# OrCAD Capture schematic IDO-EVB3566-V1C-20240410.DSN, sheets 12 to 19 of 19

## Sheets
12 P18. UART/RS232: size A3; title: IDO-SBC3566-V1B; note: UART/RS232/RS485
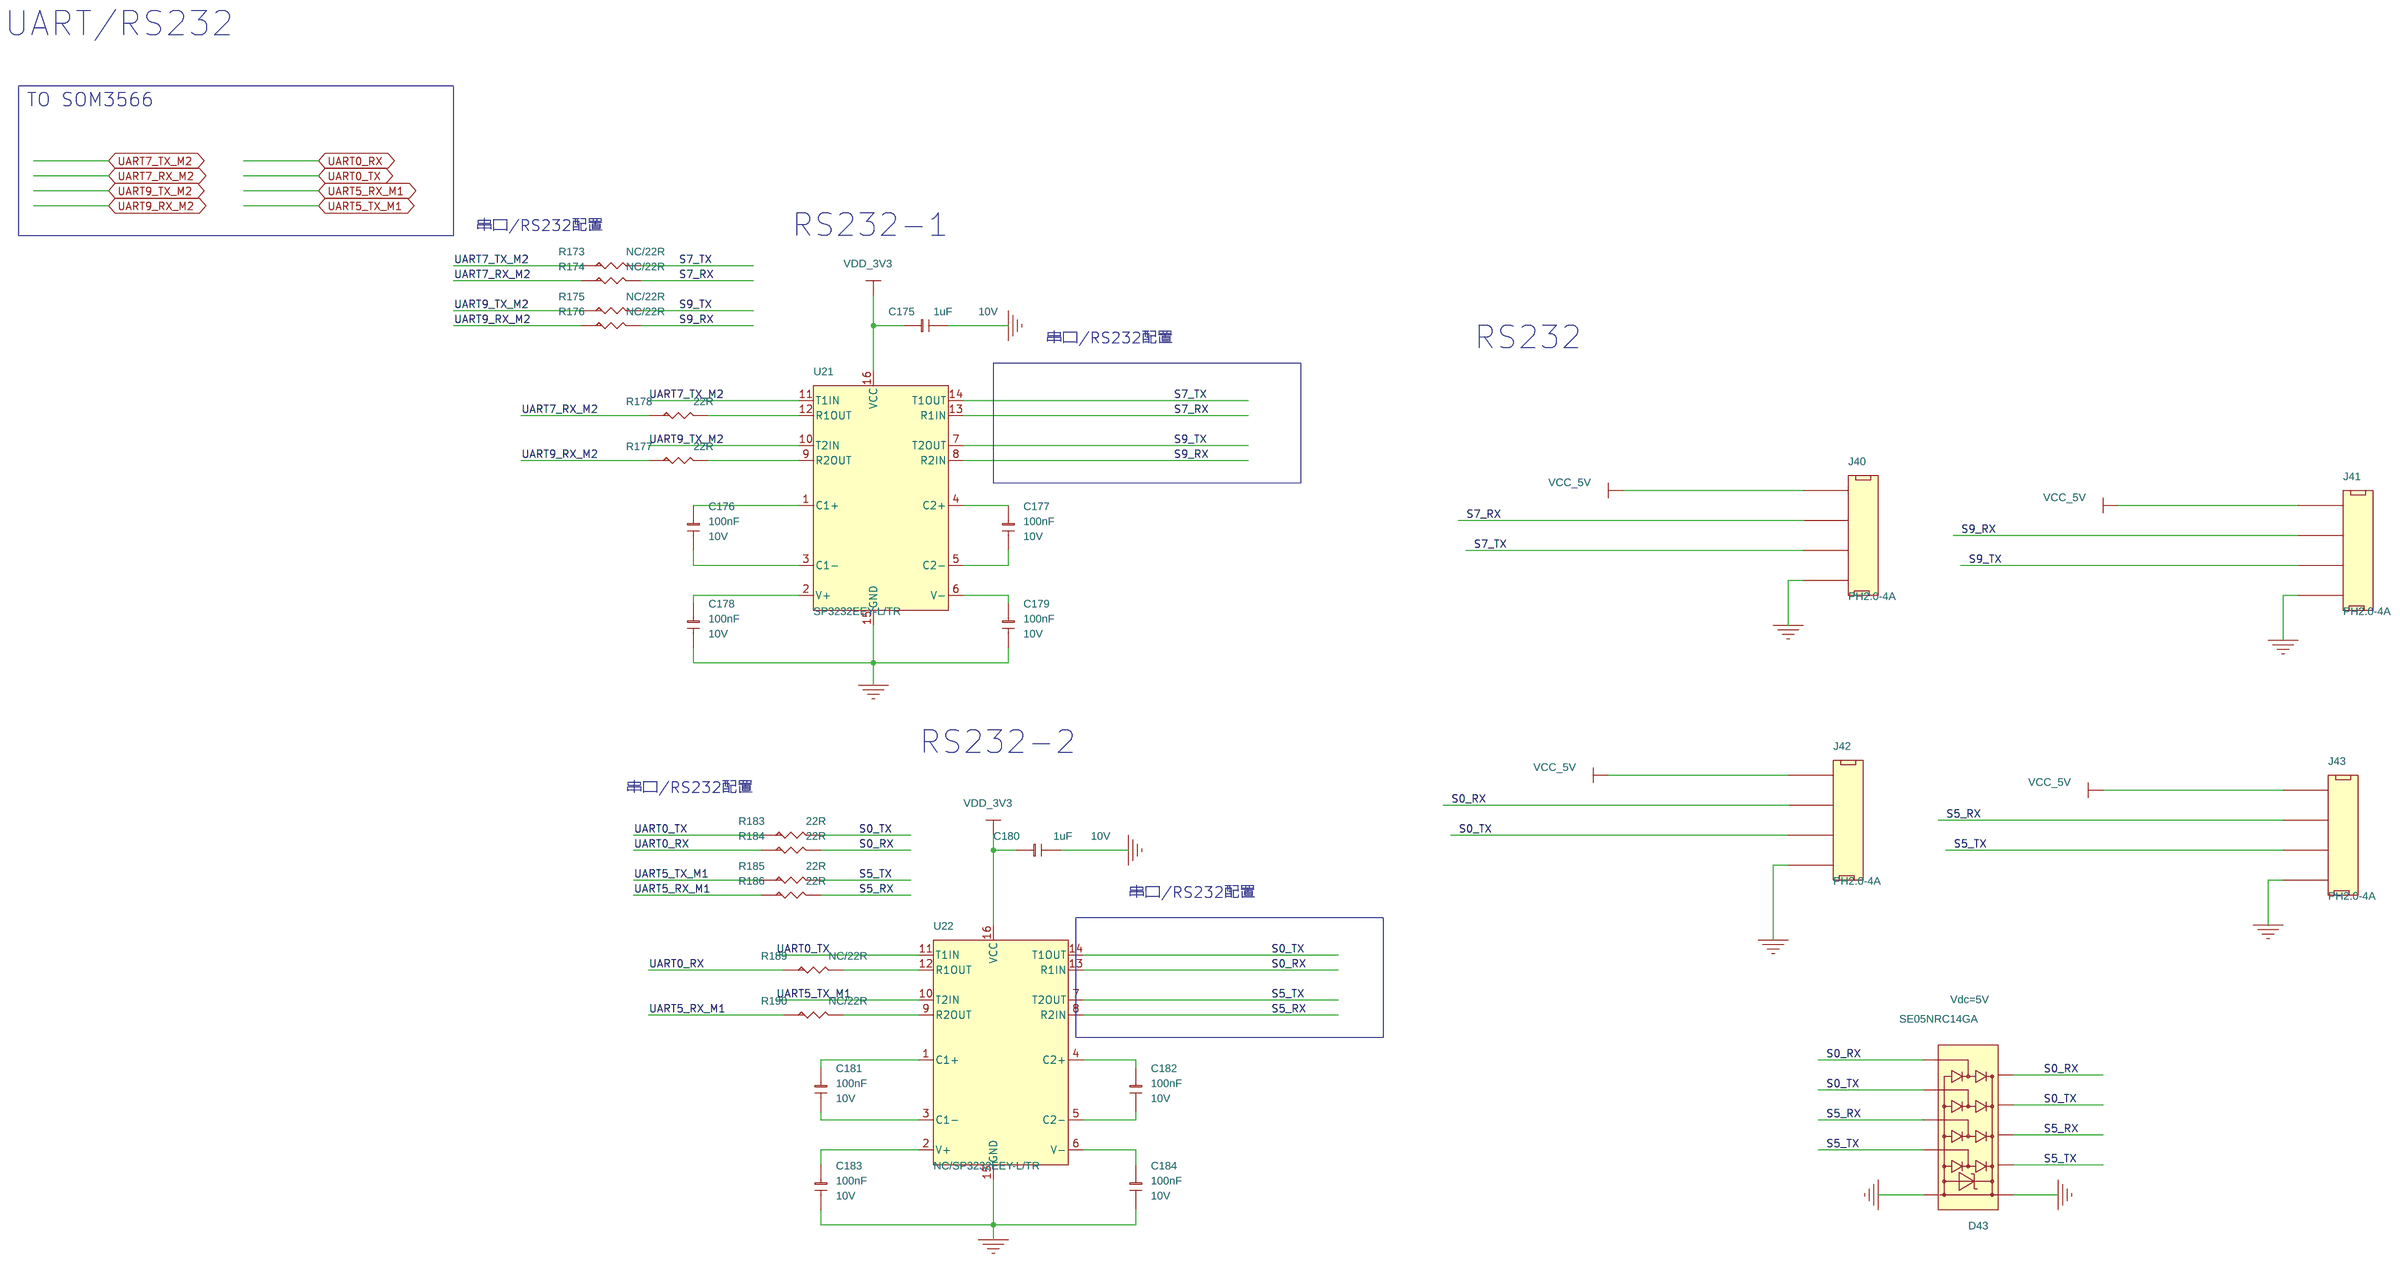
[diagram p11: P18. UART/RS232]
13 P06. RTC/KEY/ADC: size A4; title: IDO-EVB3566-V1; note: P06. RTC/KEY/ADC
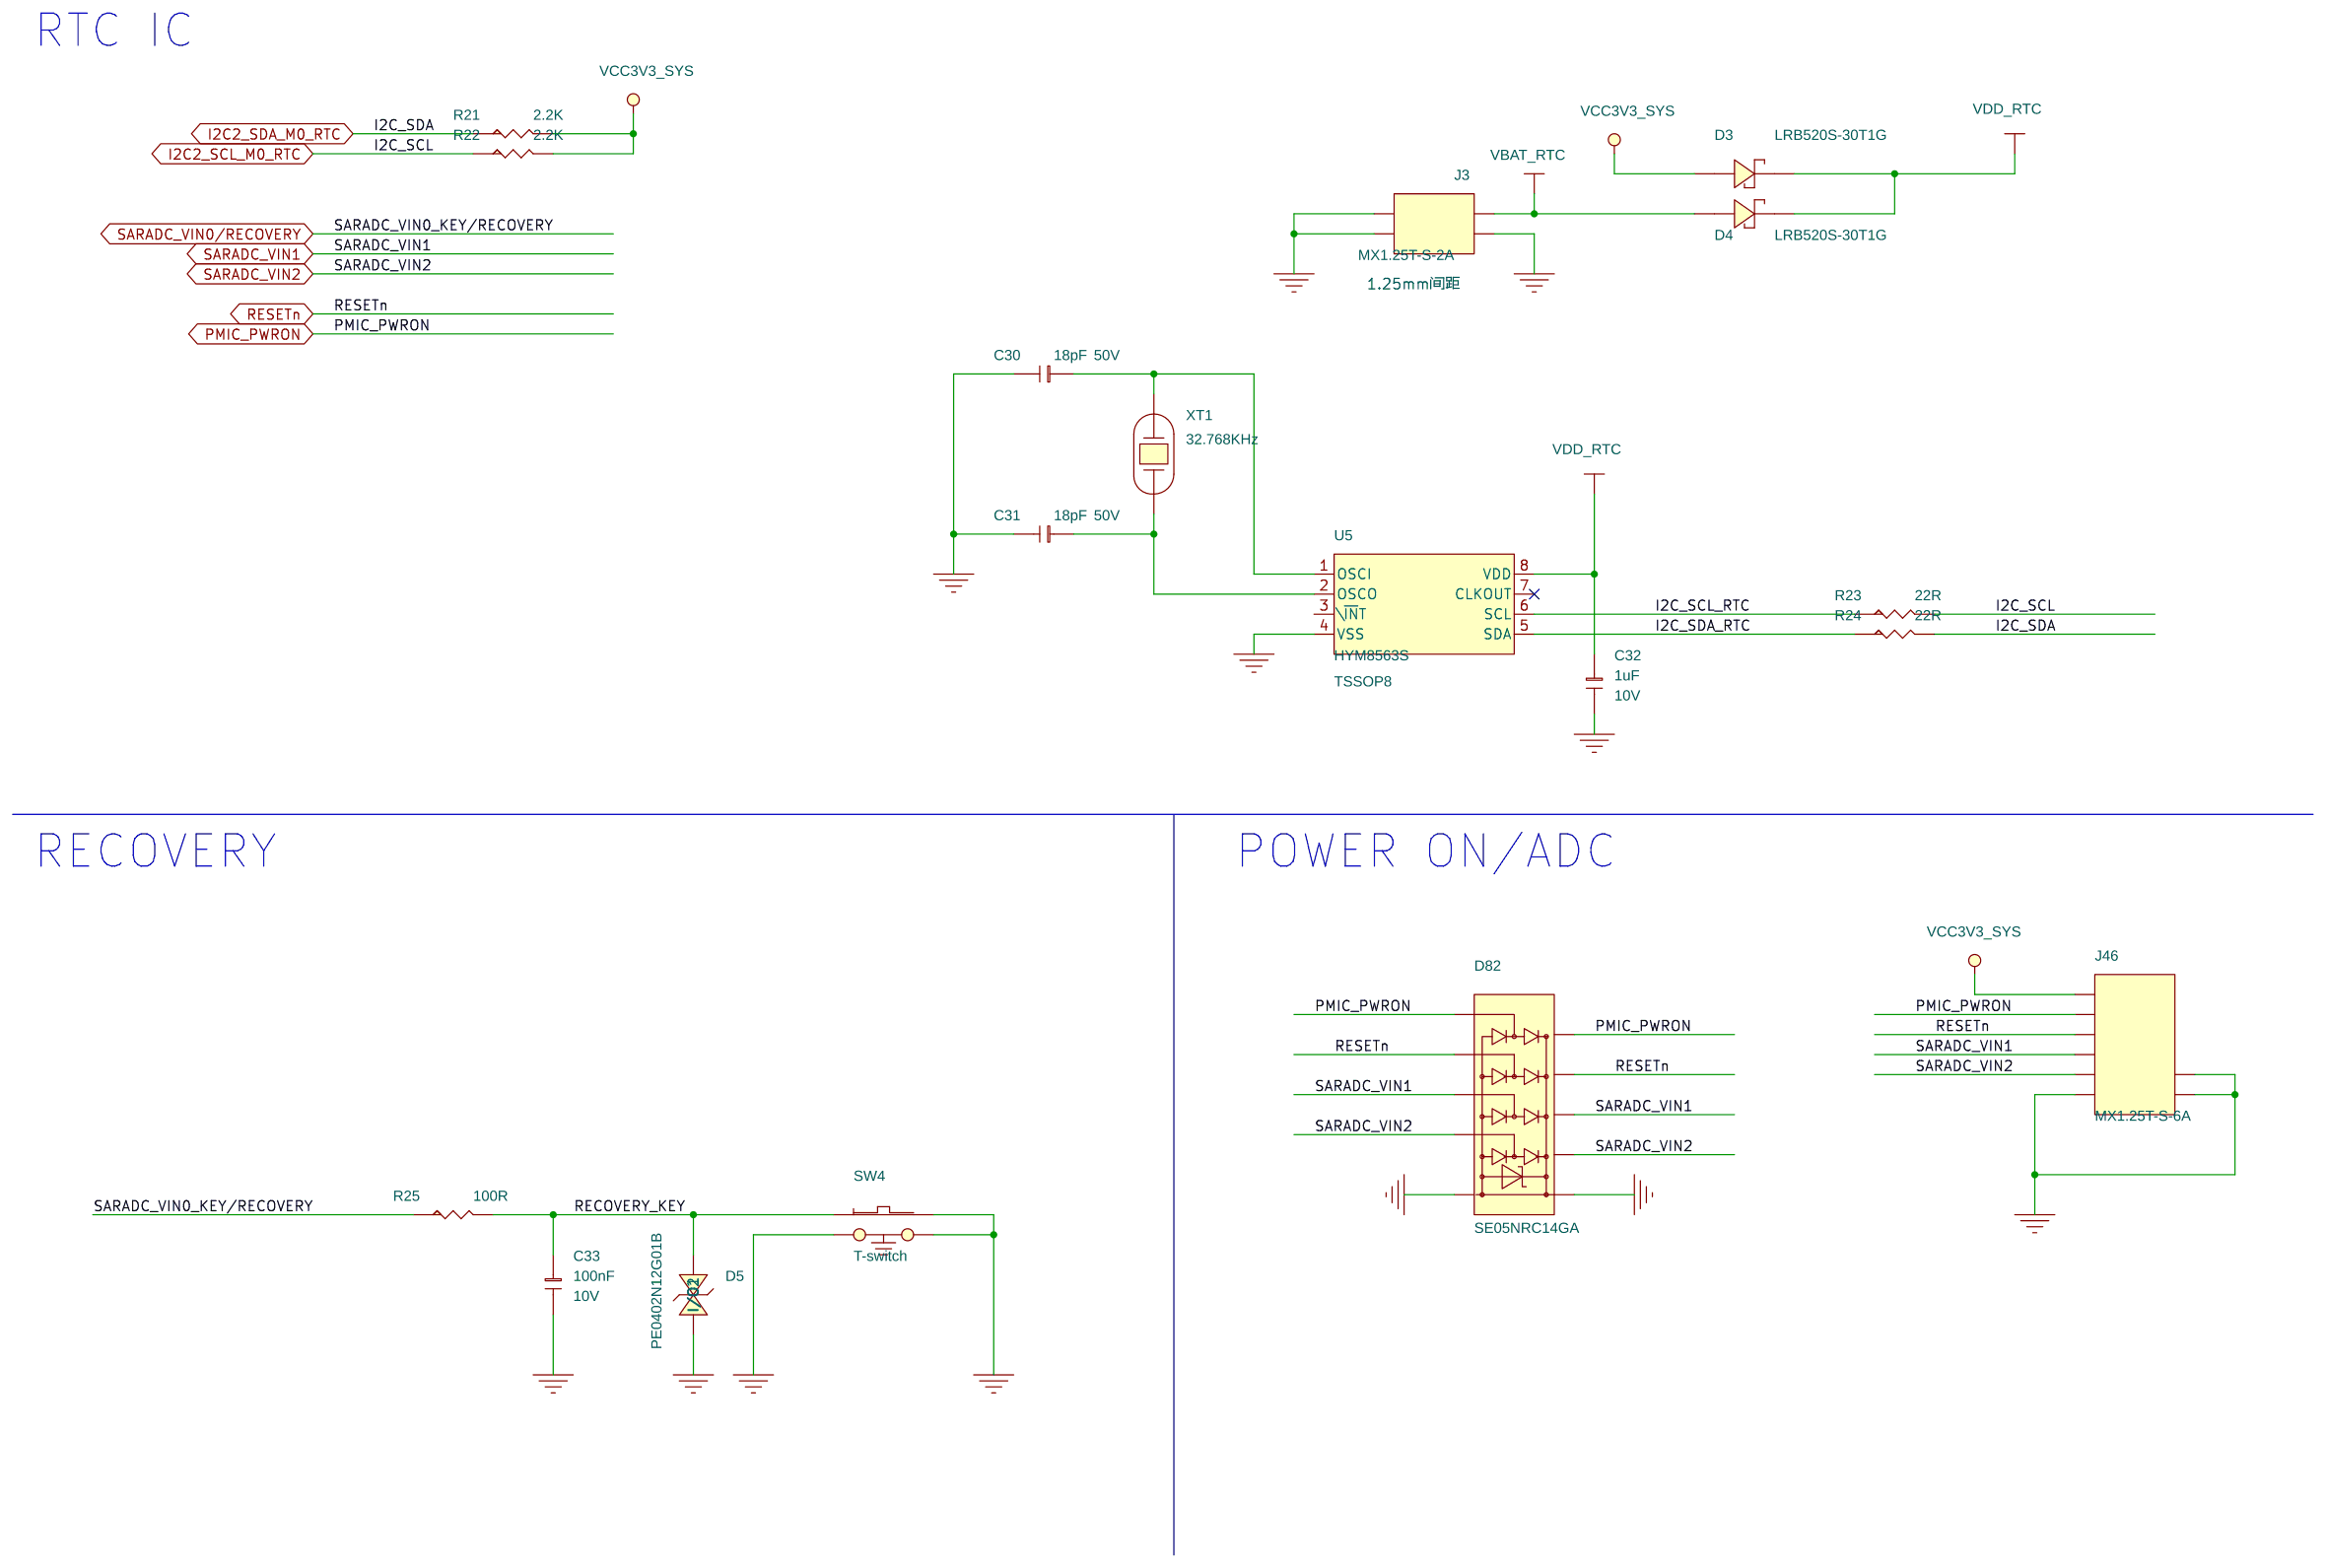
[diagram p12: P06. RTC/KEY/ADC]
14 P10. VO-MIPI-TX1/TP: size A3; title: IDO-EVB3566-V1; note: VO-LCM_MIPI_DSI_TX1
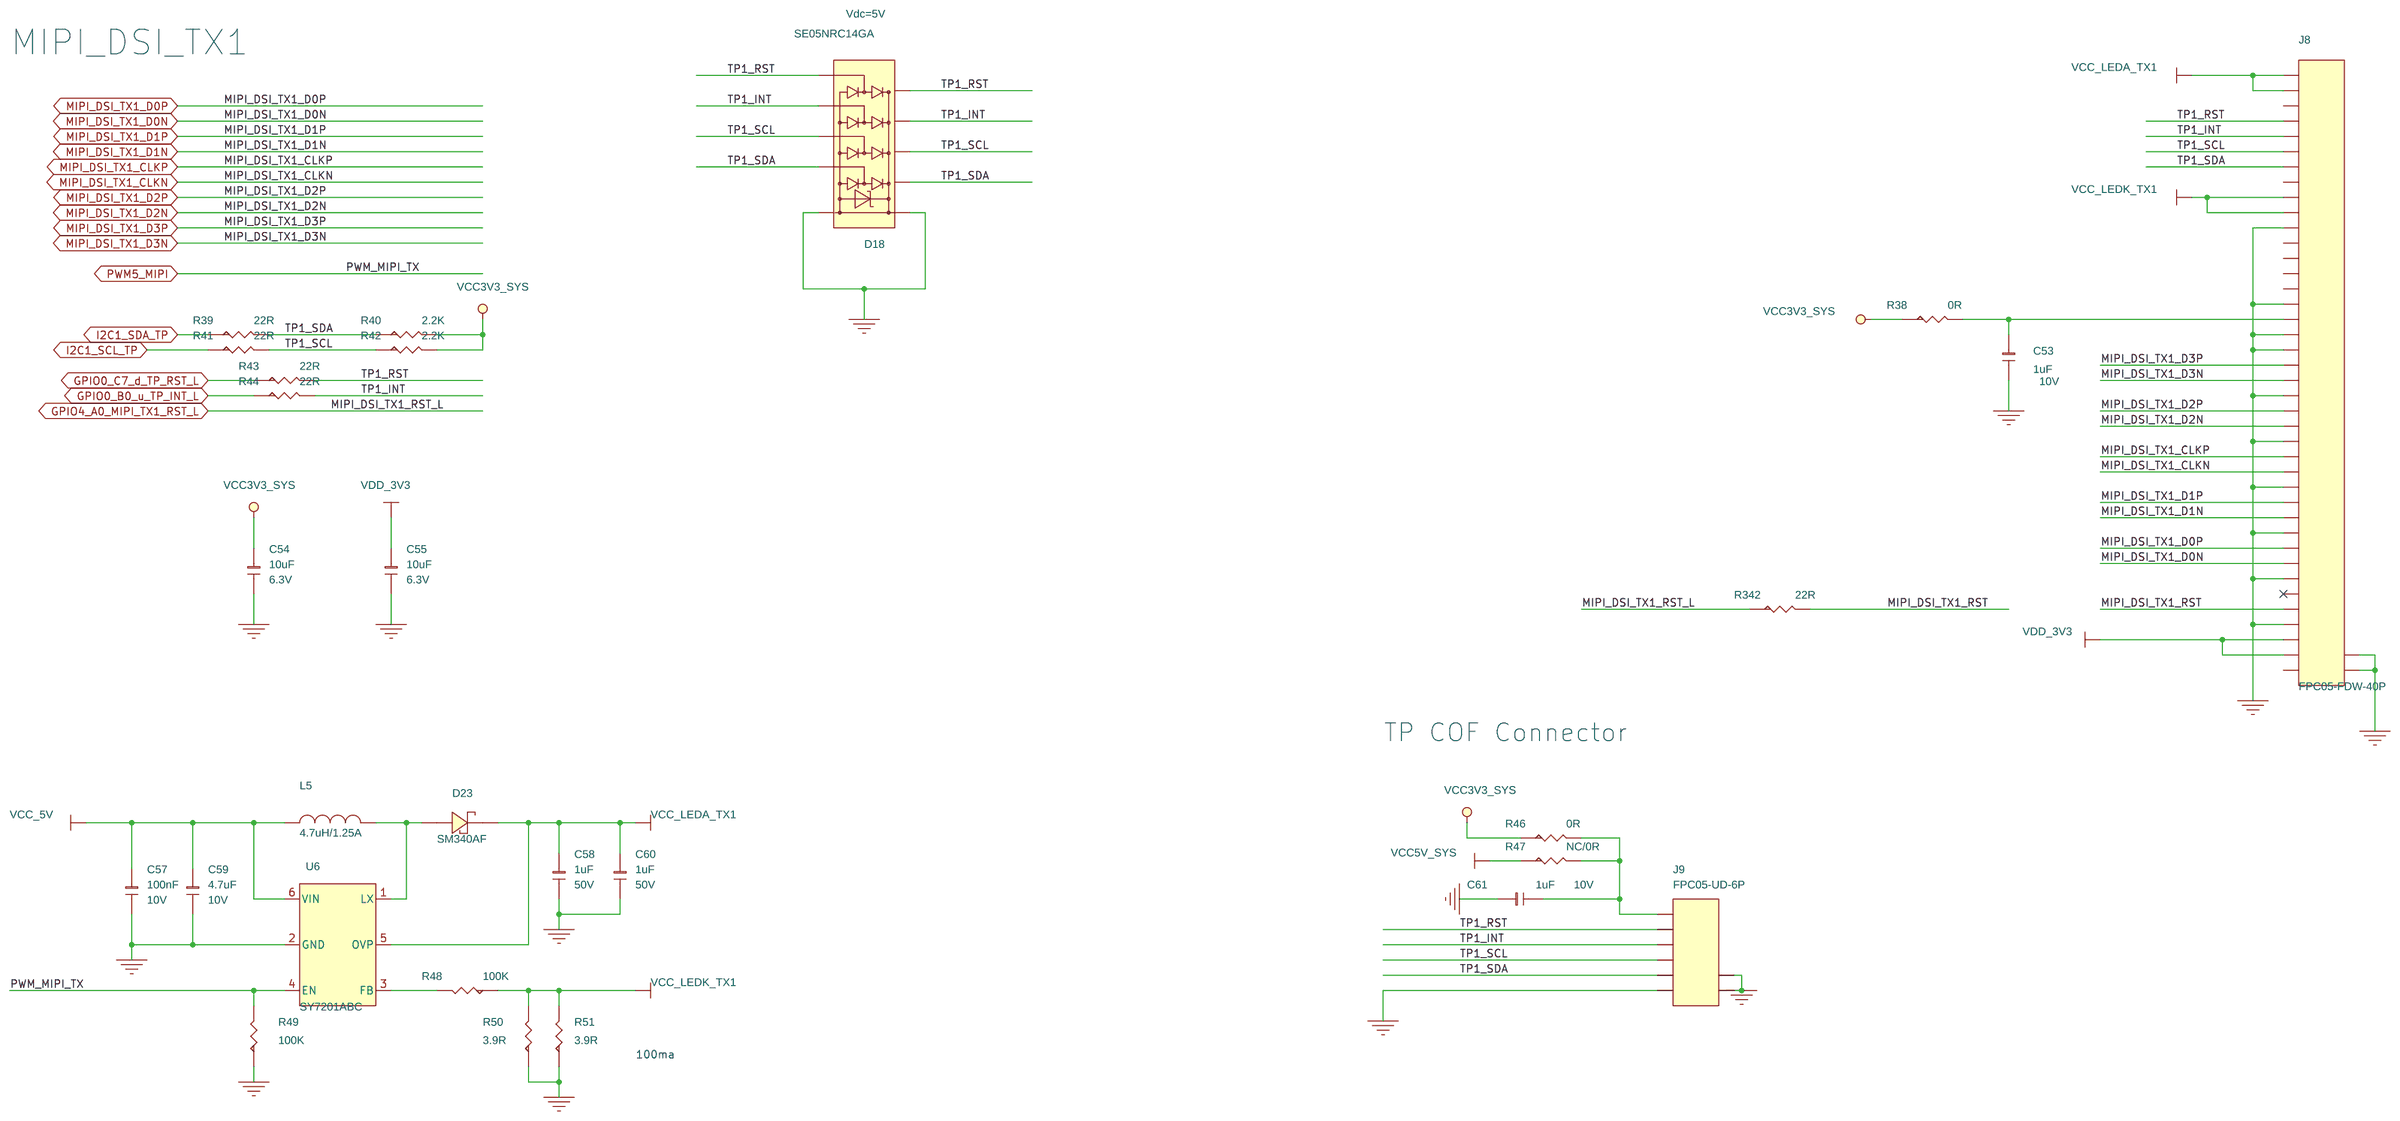
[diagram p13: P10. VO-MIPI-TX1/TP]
15 P13. 10/100M Ethernet: size A3; title: IDO-EVB3566-V1; rev: 1.0; note: 8201F-RJ45
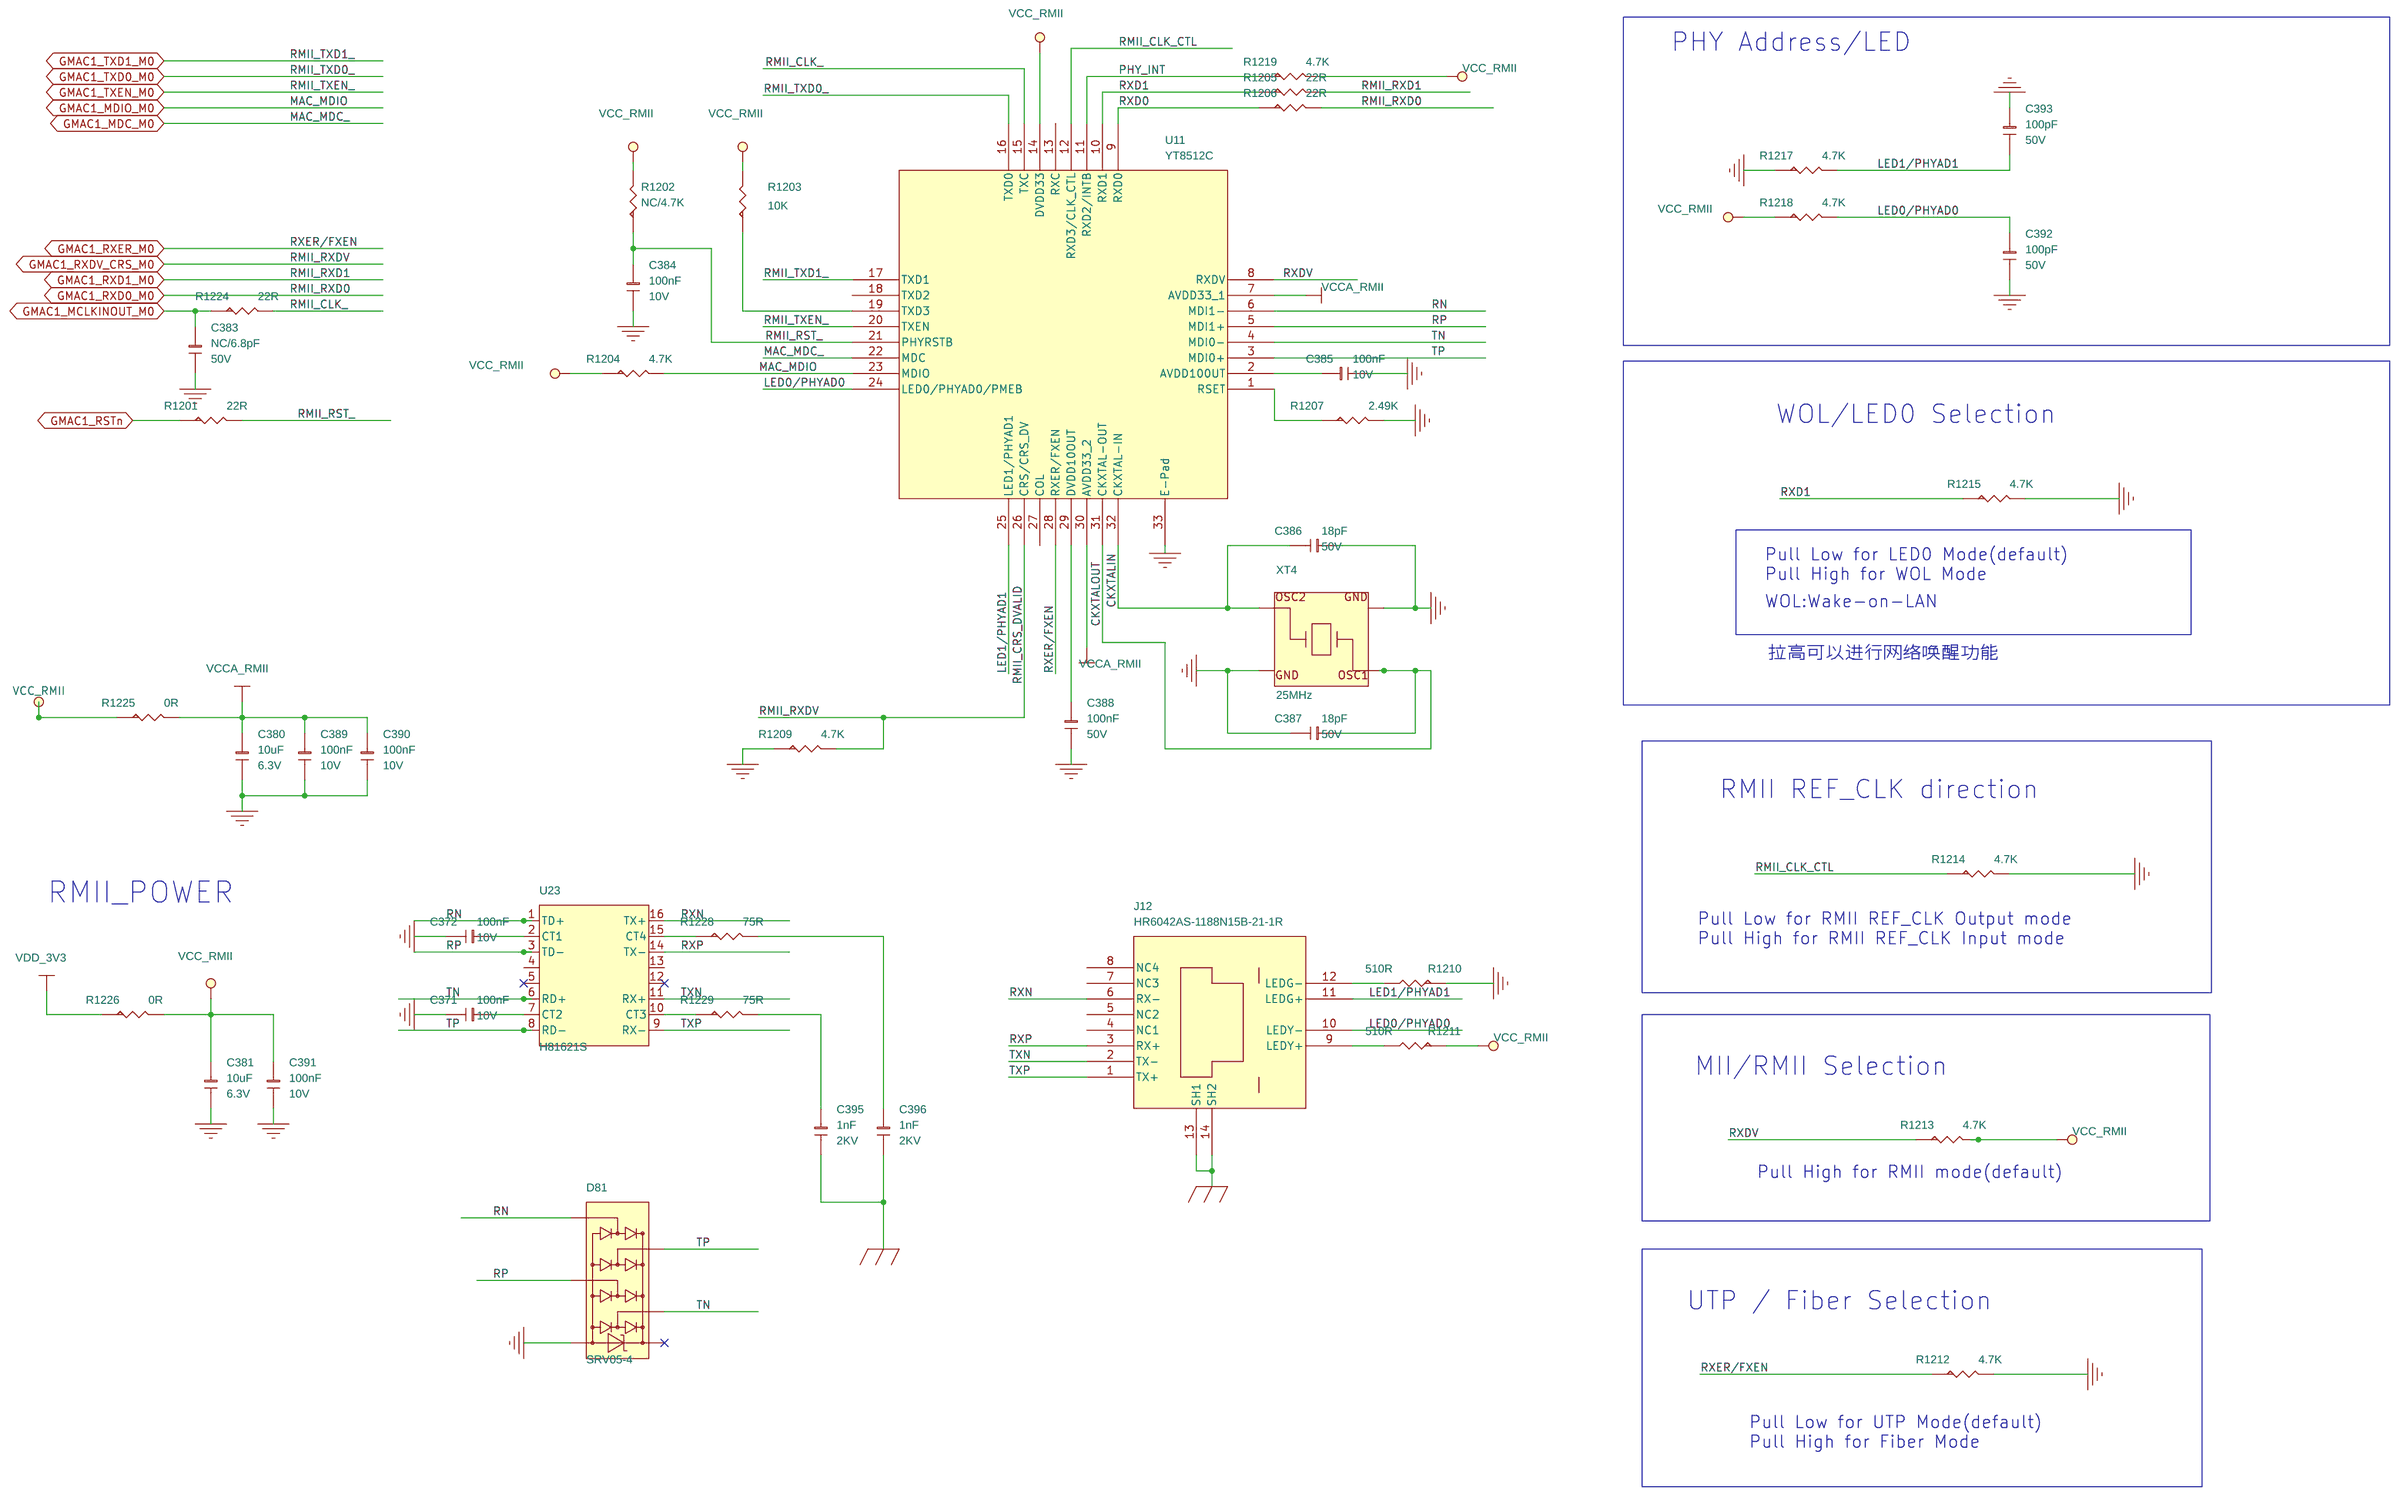
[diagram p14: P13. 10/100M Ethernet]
16 P15. HUB-FE1.1/USB HOST2: size A2; title: IDO-EVB3566-V1; note: HUB-FE2.1
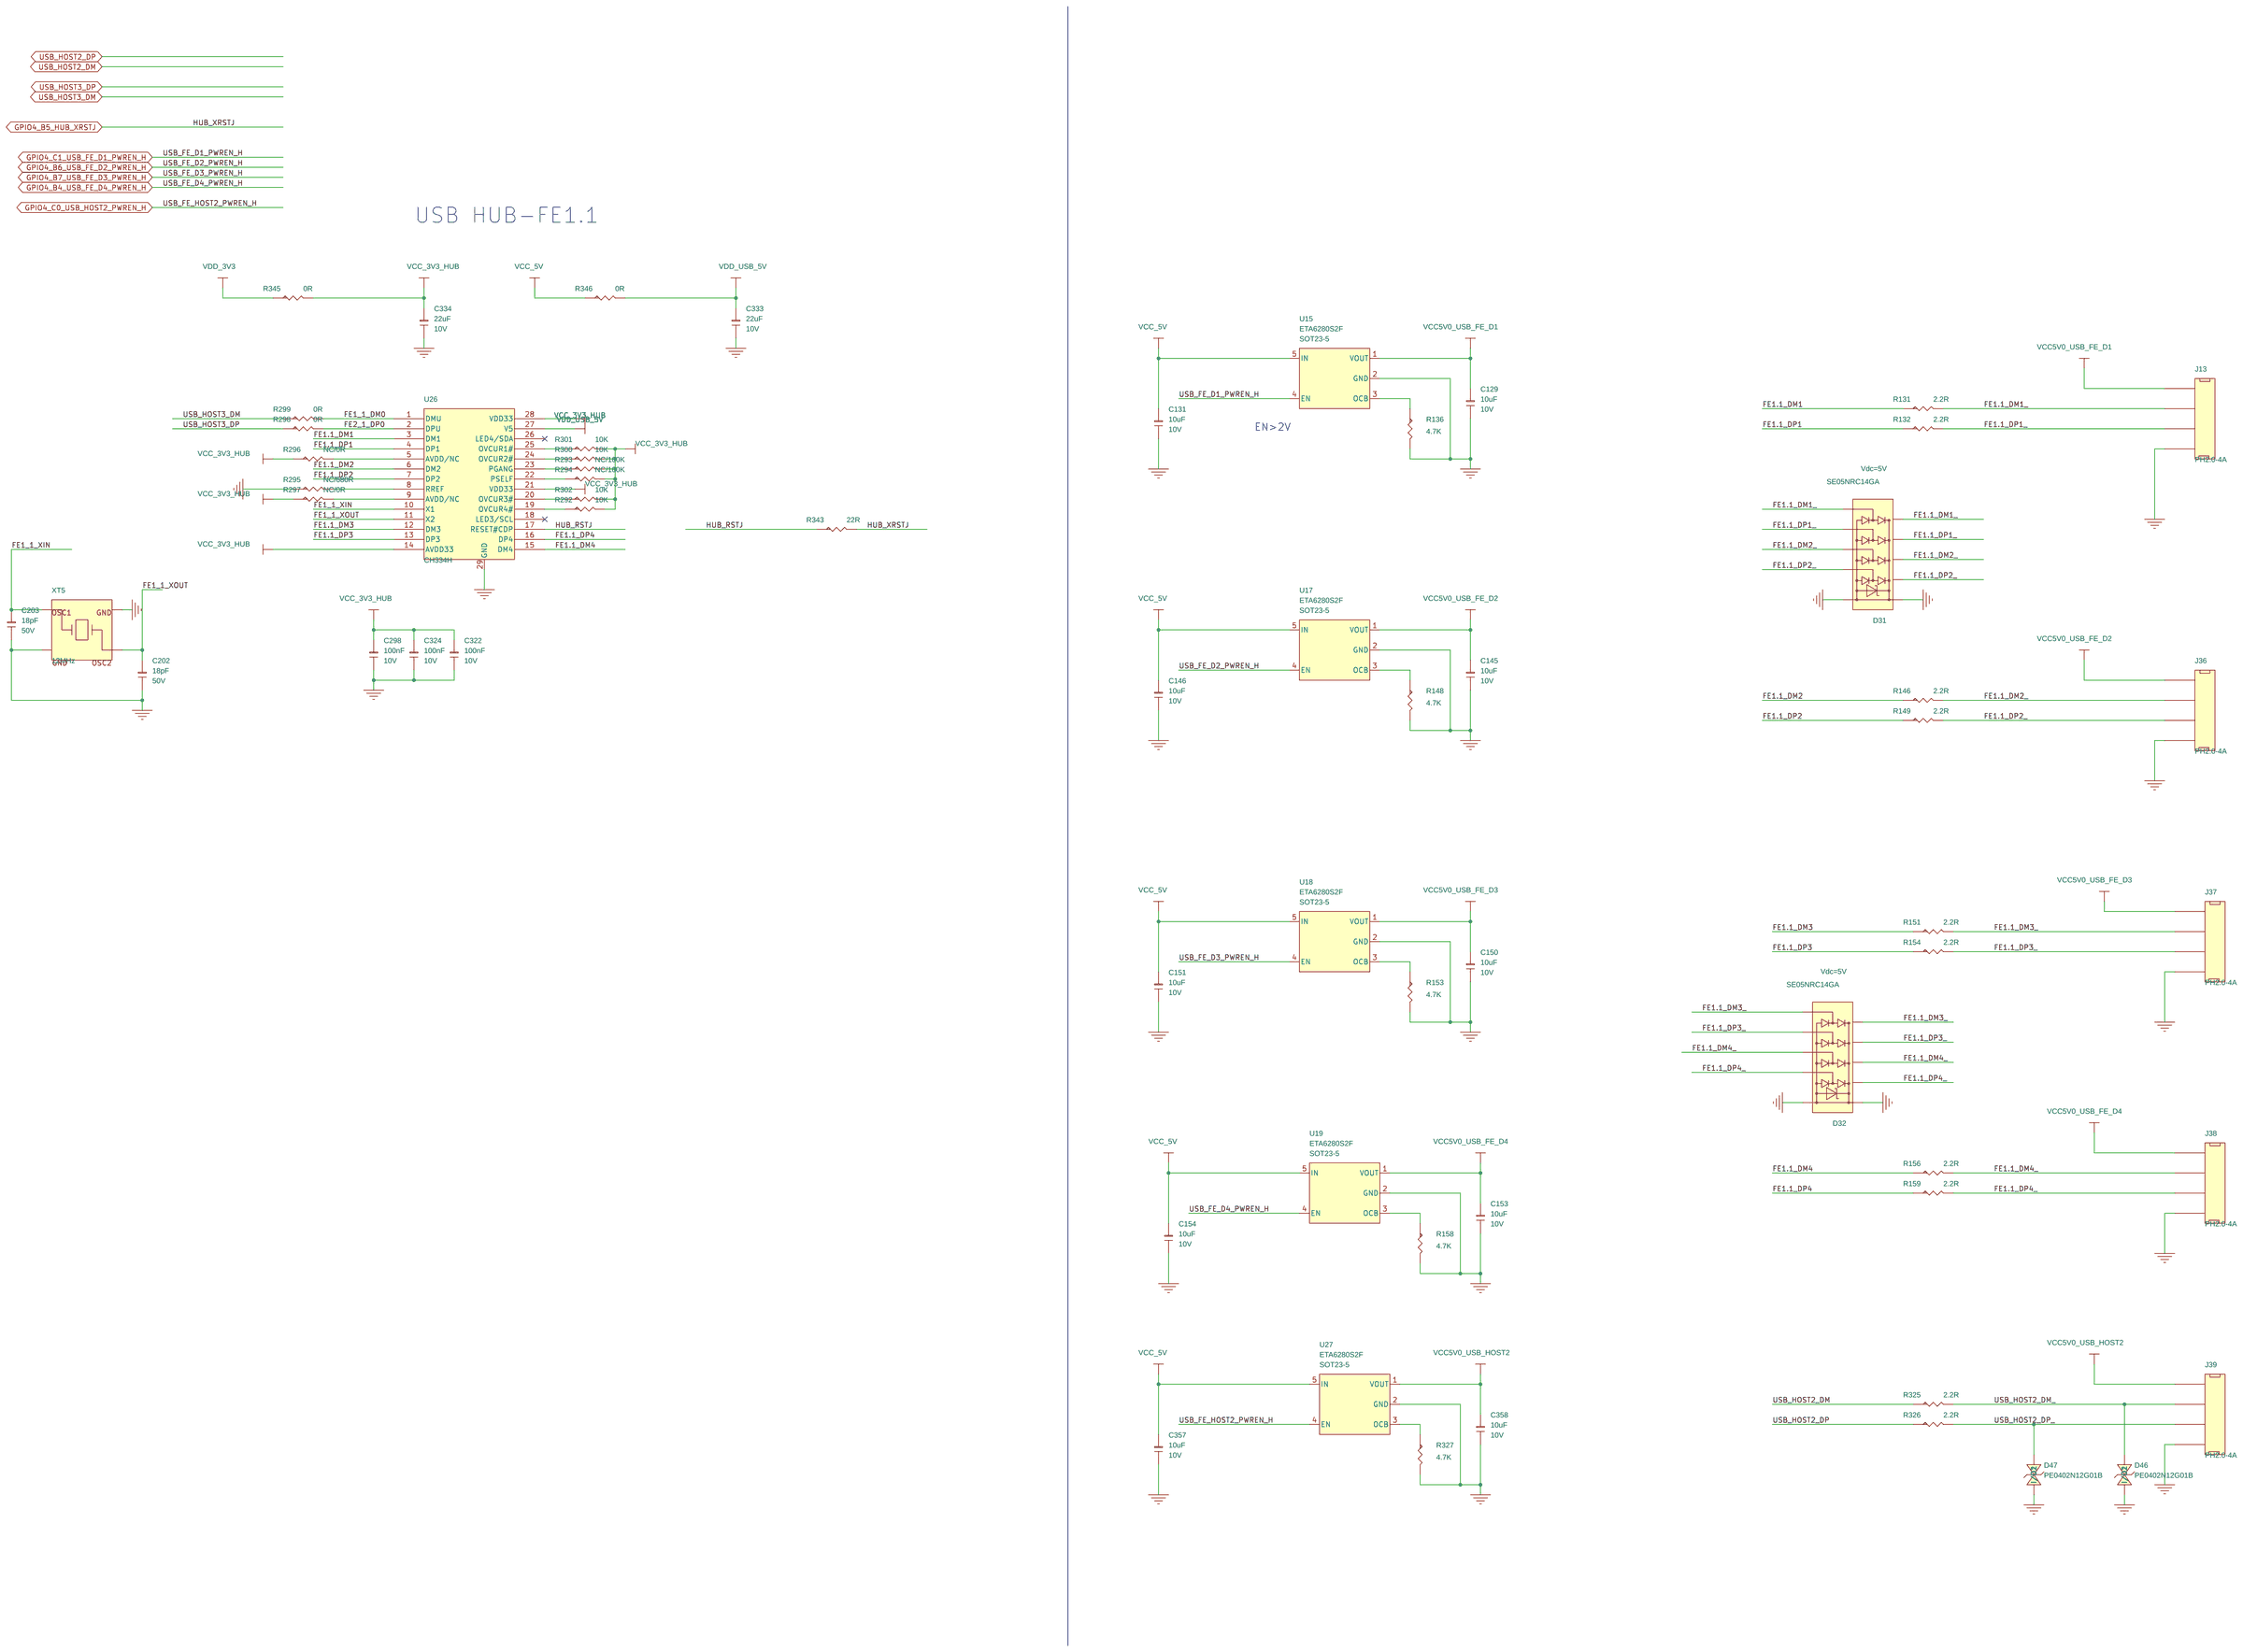
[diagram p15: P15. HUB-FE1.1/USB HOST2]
17 P14. USB3.0 HOST/USB2.0 OTG: size A3
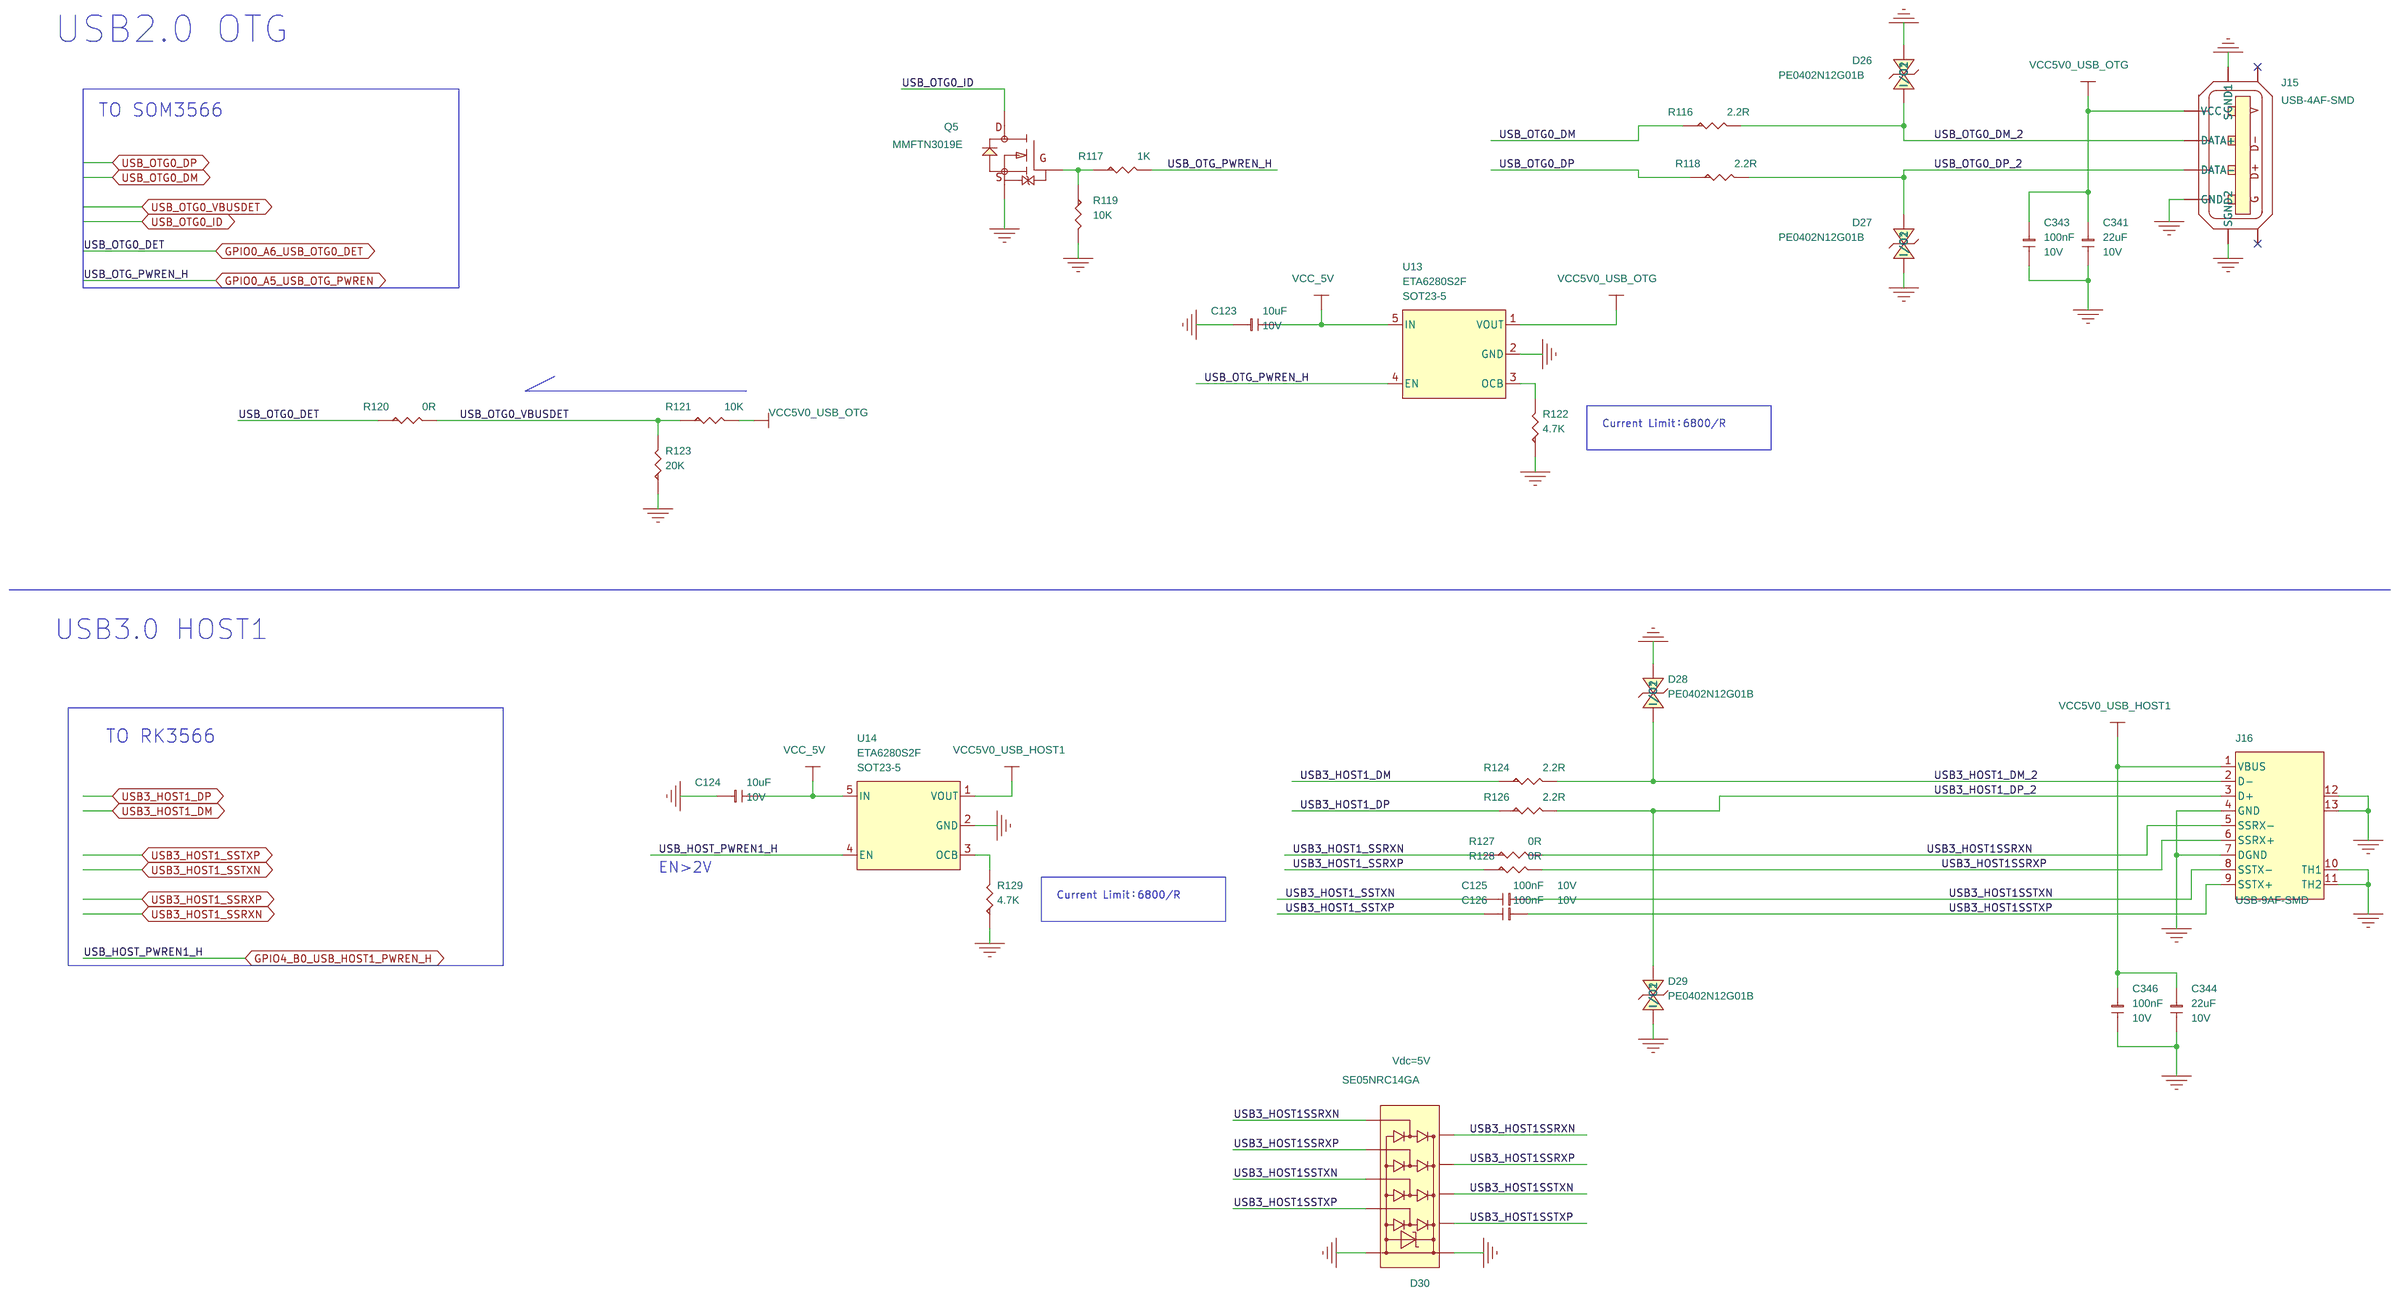
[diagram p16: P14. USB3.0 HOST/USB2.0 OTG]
18 P16. Flash-SD Card/Debug: size A4; title: IDO-EVB3566-V2; note: TF CARD & DEBUG
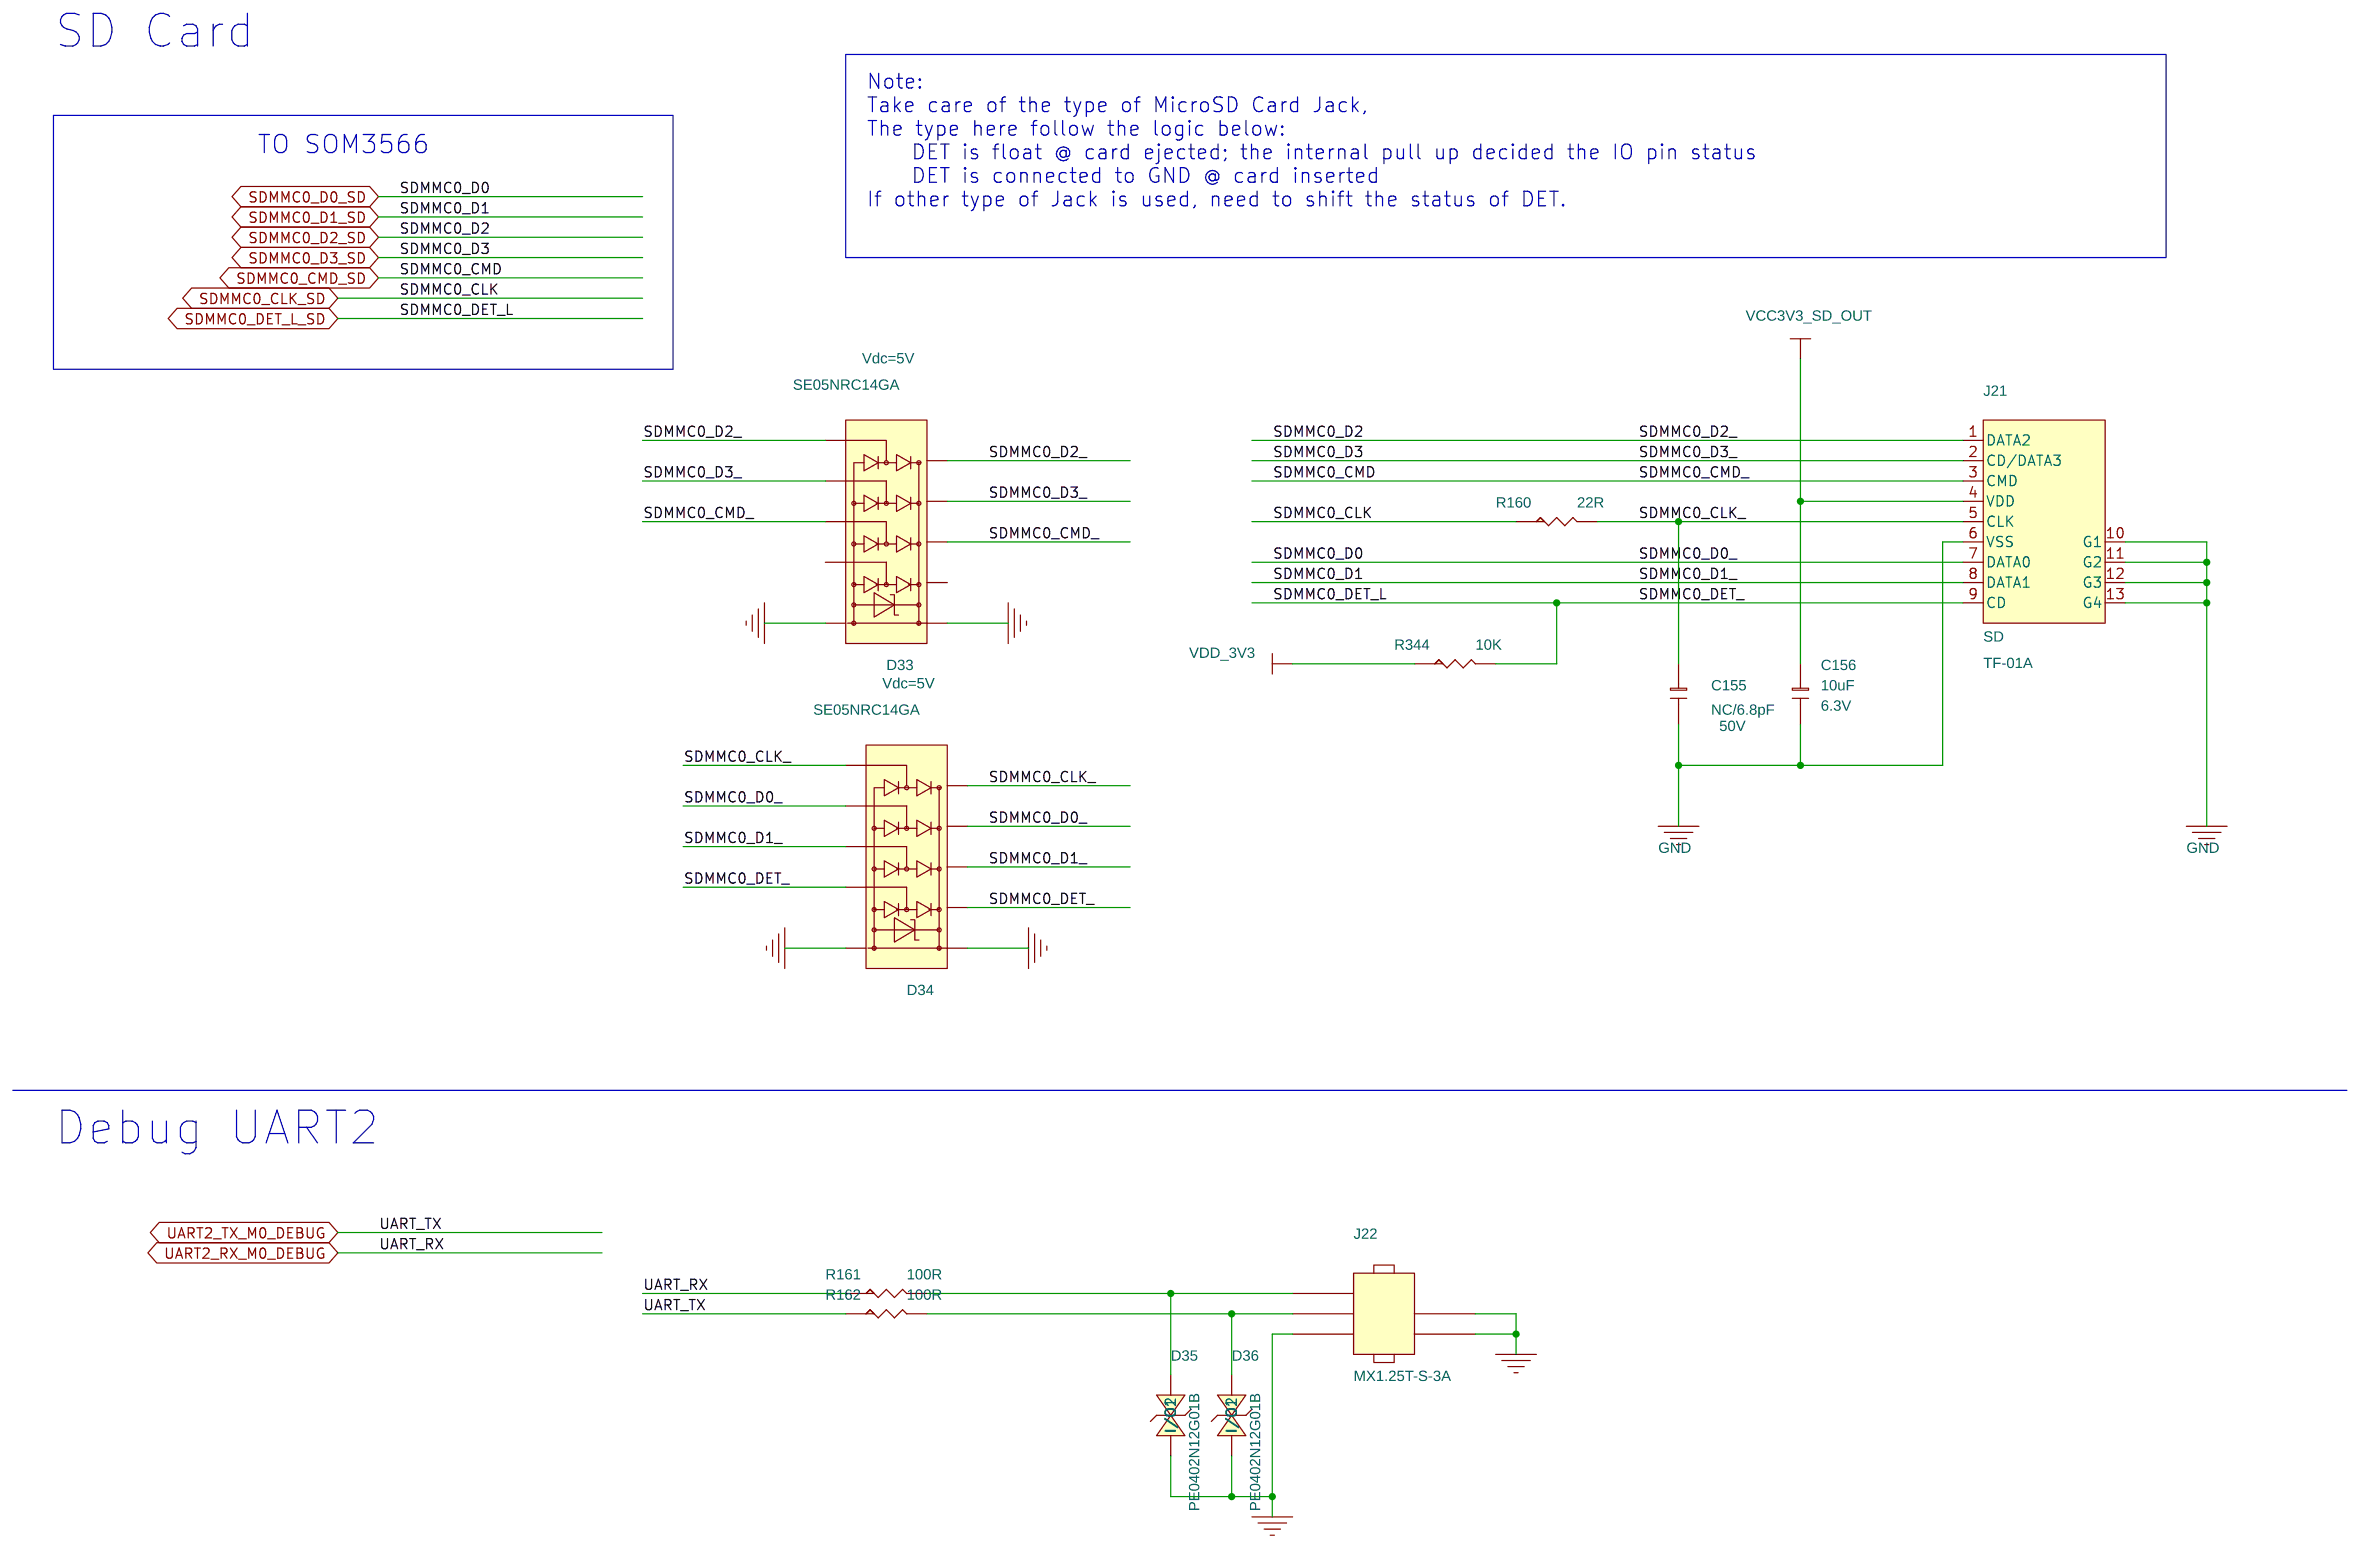
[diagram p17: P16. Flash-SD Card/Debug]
19 P12. WIFI/BT-SDMMC1_1T1R + UART: size A3; title: IDO-EVB3566-V1; note: WIFI&BT
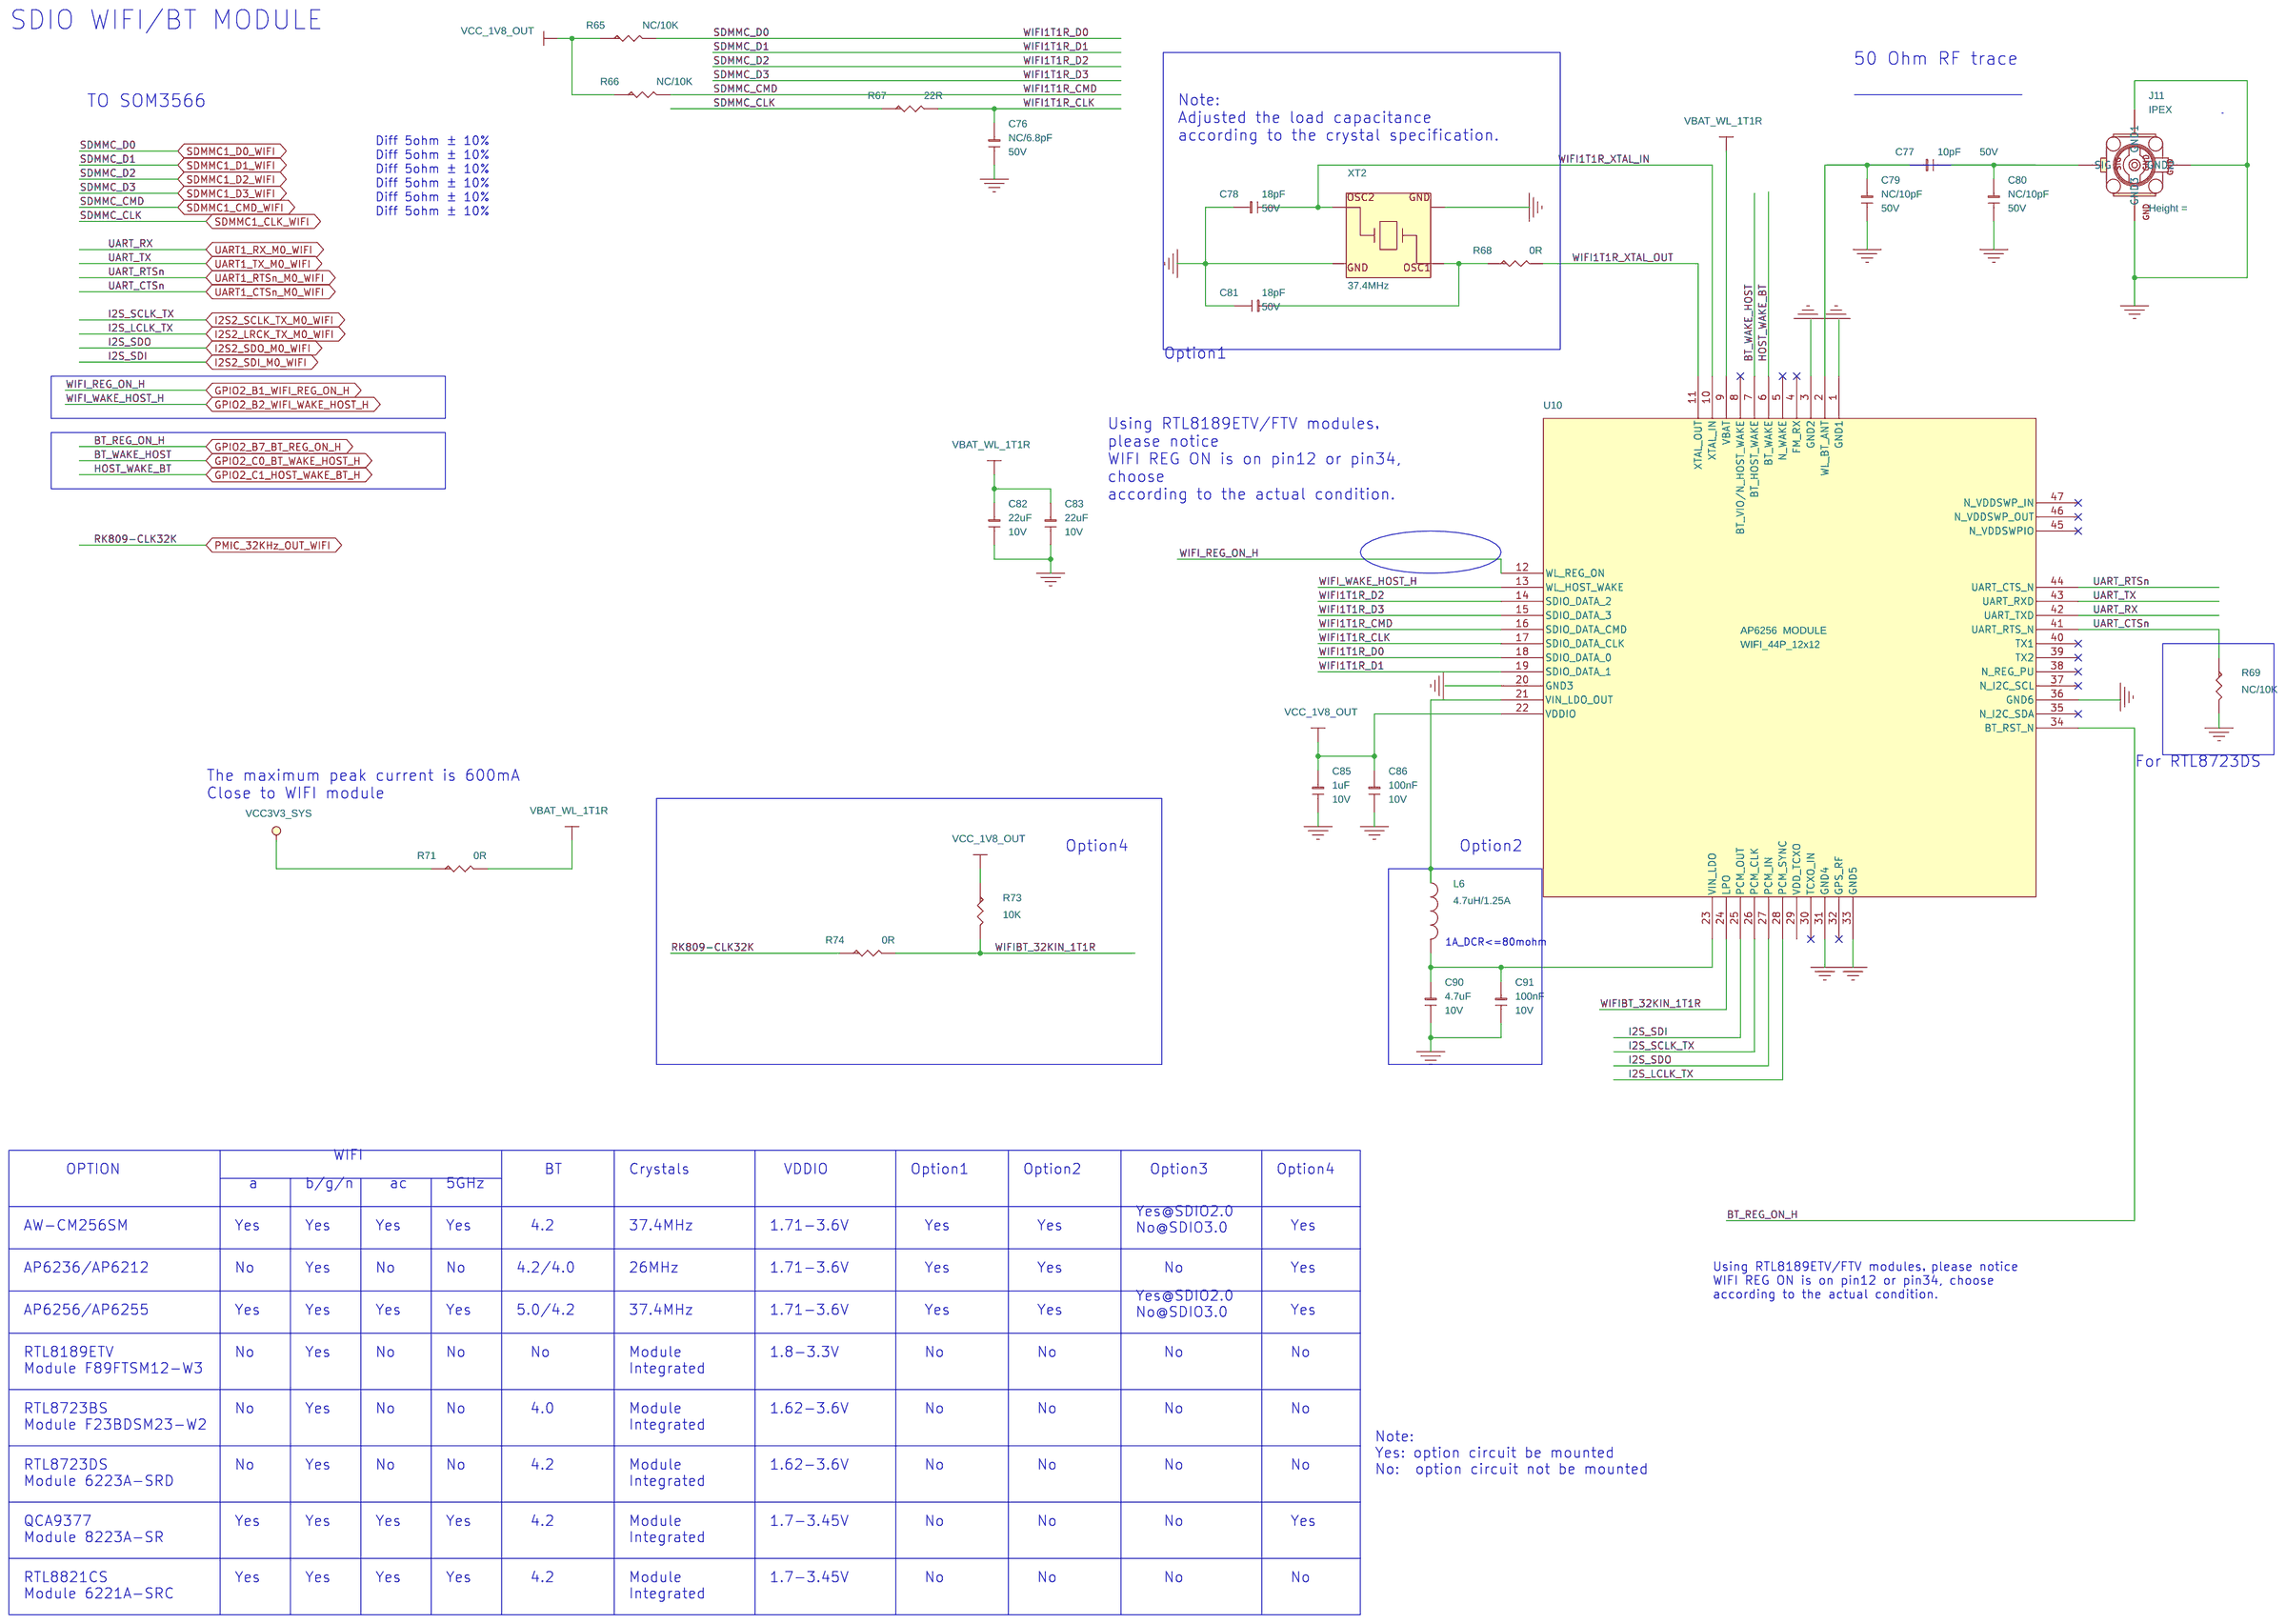
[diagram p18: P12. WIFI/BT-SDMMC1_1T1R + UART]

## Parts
sheet P06. RTC/KEY/ADC
C30  18pF  [C0402]
C31  18pF  [C0402]
C32  1uF  [C0402]
C33  100nF  [C0402]
D3  LRB520S-30T1G  [SOD523]
D4  LRB520S-30T1G  [SOD523]
D5  PE0402N12G01B  [V0402]
D82  SE05NRC14GA  [DFN2510-10L]
J3  MX1.25T-S-2A  [MX125T-S-2A]
J46  MX1.25T-S-6A  [MX125T-S-6A]
R21  2.2K  [R0402]
R22  2.2K  [R0402]
R23  22R  [R0402]
R24  22R  [R0402]
R25  100R  [R0402]
SW4  T-switch  [PB-SIDE-S-3_5x4_5]
U5  HYM8563S  [TSSOP-8]
XT1  32.768KHz  [XTAL_32X15_2P]
sheet P10. VO-MIPI-TX1/TP
C53  1uF  [C0402]
C54  10uF  [C0402]
C55  10uF  [C0402]
C57  100nF  [C0402]
C58  1uF  [C0603]
C59  4.7uF  [C0402]
C60  1uF  [C0603]
C61  1uF  [C0402]
D18  SE05NRC14GA  [DFN2510-10L]
D23  SM340AF  [SMAF]
J8  FPC05-FDW-40P  [FPC05-40P]
J9  FPC05-UD-6P  [FPC05-6P]
L5  4.7uH/1.25A  [IND_252012]
R38  0R  [R0402]
R39  22R  [R0402]
R40  2.2K  [R0402]
R41  22R  [R0402]
R42  2.2K  [R0402]
R43  22R  [R0402]
R44  22R  [R0402]
R46  0R  [R0402]
R47  NC/0R  [R0402]
R48  100K  [R0402]
R49  100K  [R0402]
R50  3.9R  [R0603]
R51  3.9R  [R0603]
R342  22R  [R0402]
U6  SY7201ABC  [SOT23-6]
sheet P12. WIFI/BT-SDMMC1_1T1R + UART
C76  NC/6.8pF  [C0402]
C77  10pF  [C0402]
C78  18pF  [C0402]
C79  NC/10pF  [C0402]
C80  NC/10pF  [C0402]
C81  18pF  [C0402]
C82  22uF  [C0603]
C83  22uF  [C0603]
C85  1uF  [C0402]
C86  100nF  [C0402]
C90  4.7uF  [C0402]
C91  100nF  [C0402]
J11  IPEX  [IPEX-001E]
L6  4.7uH/1.25A  [IND_252012]
R65  NC/10K  [R0402]
R66  NC/10K  [R0402]
R67  22R  [R0402]
R68  0R  [R0402]
R69  NC/10K  [R0402]
R71  0R  [R0603]
R73  10K  [R0402]
R74  0R  [R0402]
U10  AP6256  MODULE  [WIFI_44P_12x12]
XT2  37.4MHz  [XTAL_32X25_4P]
sheet P13. 10/100M Ethernet
C371  100nF  [C0402]
C372  100nF  [C0402]
C380  10uF  [C0402]
C381  10uF  [C0402]
C383  NC/6.8pF  [C0402]
C384  100nF  [C0402]
C385  100nF  [C0402]
C386  18pF  [C0402]
C387  18pF  [C0402]
C388  100nF  [C0402]
C389  100nF  [C0402]
C390  100nF  [C0402]
C391  100nF  [C0402]
C392  100pF  [C0402]
C393  100pF  [C0402]
C395  1nF  [C1206]
C396  1nF  [C1206]
D81  SRV05-4  [SOT23-6]
J12  HR6042AS-1188N15B-21-1R  [rj45_smd_1188N]
R1201  22R  [R0402]
R1202  NC/4.7K  [R0402]
R1203  10K  [R0402]
R1204  4.7K  [R0402]
R1205  22R  [R0402]
R1206  22R  [R0402]
R1207  2.49K  [R0402]
R1209  4.7K  [R0402]
R1210  510R  [R0402]
R1211  510R  [R0402]
R1212  4.7K  [R0402]
R1213  4.7K  [R0402]
R1214  4.7K  [R0402]
R1215  4.7K  [R0402]
R1217  4.7K  [R0402]
R1218  4.7K  [R0402]
R1219  4.7K  [R0402]
R1224  22R  [R0402]
R1225  0R  [R0402]
R1226  0R  [R0402]
R1228  75R  [R0402]
R1229  75R  [R0402]
U11  YT8512C  [QFN-32_5x5x05P]
U23  H81621S  [SOP16-P127-710X1270]
XT4  25MHz  [xtal_32x25_4p]
sheet P14. USB3.0 HOST/USB2.0 OTG
C123  10uF  [C0603]
C124  10uF  [C0603]
C125  100nF  [C0402]
C126  100nF  [C0402]
C341  22uF  [C0603]
C343  100nF  [C0402]
C344  22uF  [C0603]
C346  100nF  [C0402]
D26  PE0402N12G01B  [V0402]
D27  PE0402N12G01B  [V0402]
D28  PE0402N12G01B  [V0402]
D29  PE0402N12G01B  [V0402]
D30  SE05NRC14GA  [DFN2510-10L]
J15  USB-4AF-SMD  [USB_4A_SMD]
J16  USB-9AF-SMD  [JLX-USB-G36]
Q5  MMFTN3019E  [SOT523]
R116  2.2R  [R0402]
R117  1K  [R0402]
R118  2.2R  [R0402]
R119  10K  [R0402]
R120  0R  [R0402]
R121  10K  [R0402]
R122  4.7K  [R0402]
R123  20K  [R0402]
R124  2.2R  [R0402]
R126  2.2R  [R0402]
R127  0R  [R0402]
R128  0R  [R0402]
R129  4.7K  [R0402]
U13  ETA6280S2F  [SOT23-5]
U14  ETA6280S2F  [SOT23-5]
sheet P15. HUB-FE1.1/USB HOST2
C129  10uF  [C0603]
C131  10uF  [C0603]
C145  10uF  [C0603]
C146  10uF  [C0603]
C150  10uF  [C0603]
C151  10uF  [C0603]
C153  10uF  [C0603]
C154  10uF  [C0603]
C202  18pF  [C0402]
C203  18pF  [C0402]
C298  100nF  [C0402]
C322  100nF  [C0402]
C324  100nF  [C0402]
C333  22uF  [C0603]
C334  22uF  [C0603]
C357  10uF  [C0603]
C358  10uF  [C0603]
D31  SE05NRC14GA  [DFN2510-10L]
D32  SE05NRC14GA  [DFN2510-10L]
D46  PE0402N12G01B  [V0402]
D47  PE0402N12G01B  [V0402]
J13  PH2.0-4A  [PH200-4A]
J36  PH2.0-4A  [PH200-4A]
J37  PH2.0-4A  [PH200-4A]
J38  PH2.0-4A  [PH200-4A]
J39  PH2.0-4A  [PH200-4A]
R131  2.2R  [R0402]
R132  2.2R  [R0402]
R136  4.7K  [R0402]
R146  2.2R  [R0402]
R148  4.7K  [R0402]
R149  2.2R  [R0402]
R151  2.2R  [R0402]
R153  4.7K  [R0402]
R154  2.2R  [R0402]
R156  2.2R  [R0402]
R158  4.7K  [R0402]
R159  2.2R  [R0402]
R292  10K  [R0402]
R293  NC/100K  [R0402]
R294  NC/100K  [R0402]
R295  NC/680R  [R0402]
R296  NC/0R  [R0402]
R297  NC/0R  [R0402]
R298  0R  [R0402]
R299  0R  [R0402]
R300  10K  [R0402]
R301  10K  [R0402]
R302  10K  [R0402]
R325  2.2R  [R0402]
R326  2.2R  [R0402]
R327  4.7K  [R0402]
R343  22R  [R0402]
R345  0R  [R0603]
R346  0R  [R0603]
U15  ETA6280S2F  [SOT23-5]
U17  ETA6280S2F  [SOT23-5]
U18  ETA6280S2F  [SOT23-5]
U19  ETA6280S2F  [SOT23-5]
U26  CH334H  [QFN-28_5x5x05P]
U27  ETA6280S2F  [SOT23-5]
XT5  12MHz  [xtal_32x25_4p]
sheet P16. Flash-SD Card/Debug
C155  NC/6.8pF  [C0402]
C156  10uF  [C0402]
D33  SE05NRC14GA  [DFN2510-10L]
D34  SE05NRC14GA  [DFN2510-10L]
D35  PE0402N12G01B  [V0402]
D36  PE0402N12G01B  [V0402]
J21  SD  [TF-01A]
J22  MX1.25T-S-3A  [MX125T-S-3A]
R160  22R  [R0402]
R161  100R  [R0402]
R162  100R  [R0402]
R344  10K  [R0402]
sheet P18. UART/RS232
C175  1uF  [C0402]
C176  100nF  [C0402]
C177  100nF  [C0402]
C178  100nF  [C0402]
C179  100nF  [C0402]
C180  1uF  [C0402]
C181  100nF  [C0402]
C182  100nF  [C0402]
C183  100nF  [C0402]
C184  100nF  [C0402]
D43  SE05NRC14GA  [DFN2510-10L]
J40  PH2.0-4A  [PH200-4A]
J41  PH2.0-4A  [PH200-4A]
J42  PH2.0-4A  [PH200-4A]
J43  PH2.0-4A  [PH200-4A]
R173  NC/22R  [R0402]
R174  NC/22R  [R0402]
R175  NC/22R  [R0402]
R176  NC/22R  [R0402]
R177  22R  [R0402]
R178  22R  [R0402]
R183  22R  [R0402]
R184  22R  [R0402]
R185  22R  [R0402]
R186  22R  [R0402]
R189  NC/22R  [R0402]
R190  NC/22R  [R0402]
U21  SP3232EEY-L/TR  [TSSOP-16]
U22  NC/SP3232EEY-L/TR  [TSSOP-16]

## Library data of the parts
C30 C31 C78 C81 C202 C203 C386 C387 = C-0402: DSC1: ±5%; DSC2: 50V; DSC3: C0G; ERP Number: 1010200091; ID: 27; Manufacture: 三星|国巨|村田; Part Name: 贴片电容; Part Number: C020102120027; Price: 0.02
C32 C53 C61 C85 C175 C180 = C-0402: DSC1: ±10%; DSC2: 10V; DSC3: X5R; ERP Number: 1010200054; ID: 64; Manufacture: 三星|国巨|村田; Part Name: 贴片电容; Part Number: C020102120064; Price: 0.02
C33 C57 C86 C91 C125 C126 C298 C322 C324 = C-0402: DSC1: ±10%; DSC2: 10V; DSC3: X7R; ID: 60; Manufacture: 三星|国巨|村田; Part Name: 贴片电容; Part Number: C020102120060; Price: 0.01
D3 D4 = DI-XI-S: DSC1: VR=30V; DSC2: IF=200mA; DSC3: VF=350mV/10mA; DSC4: IR=0.5uA; ID: 2; Manufacture: 乐山无线电; Part Name: 肖特基二级管; Part Number: C040202220002; Price: 0.05; Solder: 推荐
D5 D26-D29 D35 D36 D46 D47 = DI-ESD: DSC1: 双向; DSC2: Vdc=12V; DSC4: Vc=40V; DSC5: Cj=0.05pF; ID: 1; Manufacture: 硕凯; Part Name: ESD; Part Number: C040504013980; Price: 0.06; Solder: 推荐
D18 D30-D34 D43 D82 = DI-ESD-SE05NRC14GA: DSC1: 双向; DSC2: Vdc=5V; DSC3: Vbr=8V; DSC4: Vc=20V; DSC5: Cj=0.4pF; ID: 8; Manufacture: 硕凯; Part Name: ESD; Part Number: C040504013981; Price: 0.15; Solder: 推荐
J3 = J-A-2P: DSC1: 2p; DSC2: 1.25mm间距; DSC3: 立贴; DSC4: 米黄色胶壳 耐高温; DSC5: JLX-1.25T-2AB(九龙熹); DSC6: X9821WVS-02-9TSN(星坤); ID: 6; Part Name: MX1.25T; Part Number: J020102800058
J46 = J-A-6P: DSC1: 6p; DSC2: 1.25mm间距; DSC3: 立贴; DSC4: 米黄色胶壳 耐高温; DSC5: JLX-1.25T-6AB(九龙熹); DSC6: X9821WVS-06-9TSN(星坤); Part Name: MX1.25T; Part Number: J020102800062
R21 R22 R40 R42 = R-0402: DSC1: ±5%; DSC2: 1/16W; ERP Number: 1010200170; ID: 311; Part Name: 贴片电阻; Part Number: C011002080311; Price: 0.01
R23 R24 R39 R41 R43 R44 R67 R173-R178 R183-R186 R189 R190 R342 R343 R1201 R1205 R1206 R1224 = R-0402: DSC1: ±5%; DSC2: 1/16W; ERP Number: 1010200173; ID: 262; Part Name: 贴片电阻; Part Number: C011002080262; Price: 0.01
R25 = R-0402: DSC1: ±5%; DSC2: 1/16W; ERP Number: 1010200160; ID: 279; Part Name: 贴片电阻; Part Number: C011002080279; Price: 0.01
SW4 = SW-TS24CA: DSC1: 轻触开关 侧键 贴片 带定位柱; DSC2: SMD,3.5*4.5mm; DSC3: TS24CA(首韩); ID: 4; Part Name: 轻触开关; Part Number: C180102690004
U5 = U-HYM8563S: DSC1: RTC,I2C, VCC=2.0-5.5V; DSC2: TSSOP8; DSC3: -40℃~+85℃; ID: 16; Manufacture: HAOYU(昊昱); Part Name: RTC芯片; Part Number: C110204273853
XT1 = XTAL-2P: DSC1: 70kΩ; DSC2: ±20ppm; DSC3: 12.5pF; DSC4: -40℃~+85℃; DSC5: 3.2*1.5mm 2P; ID: 2; Manufacture: 泰晶; Part Name: 贴片无源晶振; Part Number: C050102290002; Price: 0.61
C54 C55 C156 C380 C381 = C-0402: DSC1: ±20%; DSC2: 6.3V; DSC3: X5R; Manufacture: 三星|国巨|村田; Part Name: 贴片电容; Part Number: C020102120068
C58 C60 = C-0603: DSC1: ±10%; DSC2: 50V; DSC3: X5R; ERP Number: 1010200142; ID: 69; Manufacture: 三星|国巨|村田; Part Name: 贴片电容; Part Number: C020102120069; Price: 0.04
C59 C90 = C-0402: DSC1: ±20%; DSC2: 10V; DSC3: X5R; ID: 67; Manufacture: 三星|国巨|村田; Part Name: 贴片电容; Part Number: C020102120067; Price: 0.04
D23 = DI-XI-S: DSC1: VR=40V; DSC2: IF=3A; DSC3: VF=500mV/3A; ID: 7; Manufacture: 乐山无线电; Part Name: 肖特基二级管; Part Number: C040202220007; Price: 0.15; Solder: 推荐
J8 = J-FPC-40P: DSC1: 40P; DSC2: 0.5mm间距; DSC3: 下接 翻盖 卧贴; DSC4: H=2mm; DSC5: 镀锡; DSC6: X05A20L40T(星坤); Part Name: FPC座; Part Number: J030102870088
J9 = J-FPC-6P: DSC1: 6P; DSC2: 0.5mm间距; DSC3: 双面触点 前插后压 卧贴; DSC4: H=2mm; DSC5: 镀锡; DSC6: X05A20H06T（星坤）; ID: 41; Part Name: FPC座
L5 L6 = L-IND: DSC1: ±20%; DSC2: Isat=1.6A; DSC3: Irms=1.25A; DSC4: 260mΩ; DSC5: 2.5*2.0*1.2mm; DSC6: WPN252012H4R7MT(顺络); DSC7: FHD252012S-4R7MT(长江微电); DSC8: ZCRH252012-4.7uH-M(宗成); ID: 54; Manufacture: 宗成|长江微电|顺络; Part Name: 功率电感
R38 R46 R68 R74 R120 R127 R128 R296-R299 = R-0402: DSC1: ±5%; DSC2: 1/16W; ERP Number: 1010200100; ID: 217; Part Name: 贴片电阻; Part Number: C011002080217; Price: 0.01
R47 = R-0402: DSC1: ±1%; DSC2: 1/16W; ID: 413; Part Name: 贴片电阻; Part Number: C011002080413; Price: 0.01
R48 R49 = R-0402: DSC1: ±5%; DSC2: 1/16W; ERP Number: 1010200103; ID: 353; Part Name: 贴片电阻; Part Number: C011002080353; Price: 0.01
R50 R51 = R-0603: DSC1: ±1%; DSC2: 1/10W; ID: 1,232; Part Name: 贴片电阻; Part Number: C011002081232; Price: 0.01
U6 = U-SY7201A_2: DSC1: Vi=2.5-30V; DSC3: Io=2A; DSC4: Vfb=200mV; DSC5: 0.9; DSC6: 1MHz; DSC7: Boost LED驱动; ERP Number: 1010100053; ID: 24; Manufacture: 矽力杰; Part Name: DCDC; Part Number: C070202410024; Price: 1; Solder: 量产
C76 C155 C383 = C-0402: DSC1: ±0.25PF; DSC2: 50V; DSC3: C0G; ERP Number: 1010200056; ID: 18; Manufacture: 三星|国巨|村田; Part Name: 贴片电容; Part Number: C020102120018; Price: 0.01
C77 C79 C80 = C-0402: DSC1: ±5%; DSC2: 50V; DSC3: C0G; ERP Number: 1010200151; ID: 21; Manufacture: 三星|国巨|村田; Part Name: 贴片电容; Part Number: C020102120021; Price: 0.01
C82 C83 C333 C334 C341 C344 = C-0603: DSC1: ±20%; DSC2: 10V; DSC3: X5R; ID: 83; Manufacture: 三星|国巨|村田; Part Name: 贴片电容; Part Number: C020107143899; Price: 0.18
J11 = RF-IPEX-20279: DSC1: IPEX-20279-001E-01 板端贴片天线座 U.LF接头; DSC2: 贴片; ID: 1; Part Name: IPEX座; Part Number: J110103040001
R65 R66 R69 R73 R121 R292 R300-R302 = R-0402: DSC1: ±5%; DSC2: 1/16W; ERP Number: 1010200096; ID: 328; Part Name: 贴片电阻; Part Number: C011002080328; Price: 0.01
R71 R345 R346 = R-0603: DSC1: ±1%; DSC2: 1/10W; Part Name: 贴片电阻; Part Number: C011002081182
U10 = MODULE_AP6XXX: WiFi+Bluetooth 4.0(HS)+FM Rx; Created by: JJJ; Manufacturer: Ampak（正基科技）; Manufacturer PN: AP6335; Part Type: module; Priority: A; RK PN: AP6335
XT2 = XTAL-4P: DSC1: 60Ω; DSC2: ±10ppm; DSC3: 12pF; DSC4: -40℃~+85℃; DSC5: 3.2*2.5mm 4P; Manufacture: 爱普生; Part Name: 贴片无源晶振
C176-C179 C181-C184 C343 C346 C371 C372 C384 C385 C389-C391 = C-0402: DSC1: ±10%; DSC2: 10V; DSC3: X7R; ERP Number: 1010200128; ID: 61; Manufacture: 三星|国巨|村田; Part Name: 贴片电容; Part Number: C020102120061; Price: 0.05
C388 = C-0402: DSC1: ±10%; DSC2: 50V; DSC3: X7R; ERP Number: 1010200128; ID: 61; Manufacture: 三星|国巨|村田; Part Name: 贴片电容; Part Number: C020102120061; Price: 0.05
C392 C393 = C-0402: DSC1: ±5%; DSC2: 50V; DSC3: C0G; ERP Number: 1010200152; ID: 40; Manufacture: 三星|国巨|村田; Part Name: 贴片电容; Part Number: C020102120040; Price: 0.01
C395 C396 = C-1206: DSC1: ±10%; DSC2: 2KV; DSC3: X7R; Manufacture: 三星|国巨|村田; Part Name: 贴片电容; Part Number: C020102120077
D81 = DI-TVS-SRV05-4: DSC1: 单向; DSC2: Vrwm=5V; DSC3: VBR=6V; DSC4: Vc=13V; DSC5: Ipp=3.5A; DSC6: Ppp=45W; DSC7: Cj=0.36pF; ERP Number: 1010800050; ID: 15; Manufacture: 伯恩半导体; Part Name: TVS; Part Number: C040602260015; Price: 0.21; Solder: 量产
J12 = J-RJ45-MJ88B-B011-RVL11-P_2: DSC1: RJ45 8P沉板插件，双灯,沉板4.2mm,上开口,带壳全包, / 15.2x16.18x11.05 mm; DSC2: 通孔弯针; DSC3: E11S0001A-GY(华强盛); ID: 13; Part Name: RJ45
R122 R129 R1202 R1204 R1209 R1212-R1215 R1217-R1219 = R-0402: DSC1: ±5%; DSC2: 1/16W; ERP Number: 1010200177; ID: 320; Part Name: 贴片电阻; Part Number: C011002080320; Price: 0.01
R119 R344 R1203 = R-0402: DSC1: ±1%; DSC2: 1/16W; ERP Number: 1010200140; ID: 856; Part Name: 贴片电阻; Part Number: C011002080856; Price: 0.01
R1207 = R-0402: DSC1: ±1%; DSC2: 1/16W; ERP Number: 1010200324; ID: 785; Part Name: 贴片电阻; Part Number: C011002080785; Price: 0.01
R1210 R1211 = R-0402: DSC1: ±5%; DSC2: 1/16W; ERP Number: 1010200226; ID: 296; Part Name: 贴片电阻; Part Number: C011002080296; Price: 0.01
R1225 R1226 = R-0402: DSC1: ±5%; DSC2: 1/16W; Part Name: 贴片电阻; Part Number: C011002080217
R1228 R1229 = R-0402: DSC1: ±5%; DSC2: 1/16W; Part Name: 贴片电阻; Part Number: C011002080276
U11 = U-RTL8201F-VB-CG: DSC1: Physical Layer Transceivers IEEE 802.3, 10/100 Base-T/TX/FX PHY; DSC2: QFN32，5mm×5mm，0.5mm Pitch; DSC3: 0℃~+70℃; ERP Number: 1010100179; ID: 8; Manufacture: REALTEK(瑞昱); Part Name: 以太网芯片; Part Number: C100102490008
U23 = U-100M-TRANSFORMER: DSC1: 贴片 单口百兆网络变压器; DSC2: 0~70℃; DSC3: SMD,SOP16,12.8*6.9*5.6mm; Manufacture: 华强盛; Part Name: 网口变压器
XT4 = XTAL-4P: DSC1: 40Ω; DSC2: ±10ppm; DSC3: 12pF; DSC4: -40℃~+85℃; DSC5: 3.2*2.5mm 4P; Manufacture: 泰晶; Part Name: 贴片无源晶振; Part Number: C050102290006; Price: 0.48
C123 C124 C129 C131 C145 C146 C150 C151 C153 C154 C357 C358 = C-0603: DSC1: ±20%; DSC2: 10V; DSC3: X5R; ERP Number: 1010200076; ID: 71; Manufacture: 三星|国巨|村田; Part Name: 贴片电容; Part Number: C020102120071; Price: 0.05
J15 = J-USB-4AF_1: DSC1: USB-2.0，卧贴，单层，白胶，有卷边,耐高温; DSC2: 15.5*16.1*7mm; DSC3: 卧贴; DSC4: U221-041N-4V33-S5（星坤）; DSC5: JLX-USB-046（九龙熹）; ID: 3; Part Name: USB连接器; Part Number: J060102960003
J16 = J-USB-9AF-W_0: DSC1: USB-3.0，卧贴，单层，蓝胶，有卷边，耐高温; DSC3: 卧贴; ID: 12; Part Name: USB连接器
Q5 = N-MOS-Q: DSC1: Vds=30V; DSC2: Id=100mA; DSC3: Vgs(th)=1.5V; DSC4: Vgs=±20V; DSC5: pd=150mW; ERP Number: 1010800011; ID: 4; Manufacture: 先科; Part Name: N-MOS; Part Number: C030202190004; Price: 0.1
R116 R118 R124 R126 R131 R132 R146 R149 R151 R154 R156 R159 R325 R326 = R-0402: DSC1: ±5%; DSC2: 1/16W; ERP Number: 1010200263; ID: 238; Part Name: 贴片电阻; Part Number: C011002080238; Price: 0.01
R117 = R-0402: DSC1: ±5%; DSC2: 1/16W; ERP Number: 1010200104; ID: 303; Part Name: 贴片电阻; Part Number: C011002080303; Price: 0.01
R123 = R-0402: DSC1: ±5%; DSC2: 1/16W; ERP Number: 1010200258; ID: 332; Part Name: 贴片电阻; Part Number: C011002080332; Price: 0.01
U13-U15 U17-U19 U27 = U-SY6280AAC: DSC1: 低能耗电源开关; DSC2: 2.4-5.5V 2A; DSC3: 80mA; DSC4: -40~85℃; ID: 1; Manufacture: ETA; Part Name: 功率开关; Price: 0.42
J13 J36-J43 = J-H-4P_0: DSC1: 4p; DSC2: 2.0mm间距; DSC3: 通孔180度直针; DSC4: 米黄色胶壳 耐高温; DSC5: A2001WV-4P(CJT); ID: 13; Part Name: PH; Part Number: J020302820003
R136 R148 R153 R158 R327 = R-0402: DSC1: ±5%; DSC2: 1/16W; Part Name: 贴片电阻; Part Number: C011002080320
R293 R294 = R-0402: DSC1: ±1%; DSC2: 1/16W; ERP Number: 1010200137; ID: 976; Part Name: 贴片电阻; Part Number: C011002080976; Price: 0.01
R295 = R-0402: DSC1: ±1%; DSC2: 1/16W; ERP Number: 1010200186; ID: 723; Part Name: 贴片电阻; Part Number: C011002080723; Price: 0.01
U26 = U-GL850G-60_2: DSC1: USB2.0 HUB 4Ports; DSC2: SSOP-28，0.65mm Pitch; DSC3: -55℃~+100℃; ID: 38; Manufacture: GENESYS(创惟); Part Name: USB芯片; Part Number: C100202500011
XT5 = XTAL-4P: DSC1: 100Ω; DSC2: ±10ppm; DSC3: 12pF; DSC4: -40℃~+85℃; DSC5: 3.2*2.5mm 4P; ERP Number: 1010700002; ID: 4; Manufacture: 泰晶; Part Name: 贴片无源晶振; Part Number: C050102290004; Price: 0.45
J21 = J-TF-01A: DSC1: 自弹式 MicroSD卡(TF卡) 卡座 外焊 外扣,无弹片 本体最大高度：2mm; DSC3: 贴片; DSC4: KLM-1007（九龙熹）; DSC5: XKTF-N02-N(星坤); ID: 2; Part Name: SD卡座; Part Number: J080102980002
J22 = J-A-3P: DSC1: 3p; DSC2: 1.25mm间距; DSC3: 立贴; DSC4: 米黄色胶壳 耐高温; DSC5: A1251WV-S-3P(CJT); ID: 7; Part Name: MX1.25T; Part Number: J020102800059
R160 = R-0402: DSC1: ±5%; DSC2: 1/16W; ERP Number: 1010200173; Part Name: 贴片电阻; Part Number: C011002080262; Price: 0.01
R161 R162 = R-0402: DSC1: ±1%; DSC2: 1/16W; ERP Number: 1010200450; ID: 630; Part Name: 贴片电阻; Part Number: C011002080630; Price: 0.01
U21 U22 = U-SP3232EEN: DSC1: RS232 Transceiver up to 235kbps; DSC2: TSSOP-16，0.65mm Pitch; DSC3: -40℃~+85℃; ID: 49; Manufacture: Maxlinear; Part Name: RS232/RS485芯片; Part Number: C100308133921; Price: 0.91

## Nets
GND: C30.1 C31.1 C32.1 C33.1 C53.1 C54.1 C55.1 C57.1 C58.1 C59.1 C60.1 C61.2 C76.1 C78.2 C79.1 C80.1 C81.1 C82.1 C83.1 C85.1 C86.1 C90.1 C91.1 C123.2 C124.2 C129.1 C131.1 C145.1 C146.1 C150.1 C151.1 C153.1 C154.1 C155.1 C156.1 C175.1 C178.1 C179.1 C180.1 C183.1 C184.1 C202.1 C203.1 C298.1 C322.1 C324.1 C333.1 C334.1 C341.1 C343.1 C344.1 C346.1 C357.1 C358.1 C371.1 C372.1 C380.1 C381.1 C383.1 C384.1 C385.1 C386.2 C387.1 C388.1 C389.1 C390.1 C391.1 C392.1 C393.2 D5.2(I/O1) D18.3 D18.8 D26.1(I/O2) D27.2(I/O1) D28.1(I/O2) D29.2(I/O1) D30.3 D30.8 D31.3 D31.8 D32.3 D32.8 D33.3 D33.8 D34.3 D34.8 D35.1(I/O2) D36.1(I/O2) D43.3 D43.8 D46.2(I/O1) D47.2(I/O1) D81.2 D82.3 D82.8 J3.2 J3.3 J3.4 J8.11 J8.16 J8.18 J8.19 J8.22 J8.25 J8.28 J8.31 J8.34 J8.37 J8.41 J8.42 J9.6 J9.7 J9.8 J11.1(GND1) J11.3(GND2) J11.4(GND3) J13.4 J15.4(GND) J15.5(SGND1) J15.6(SGND2) J16.4(GND) J16.7(DGND) J16.10(TH1) J16.11(TH2) J16.12 J16.13 J21.6(VSS) J21.10(G1) J21.11(G2) J21.12(G3) J21.13(G4) J22.3 J22.4 J22.5 J36.4 J37.4 J38.4 J39.4 J40.4 J41.4 J42.4 J43.4 J46.6 J46.7 J46.8 Q5.2(SOURCE) R49.1 R50.1 R51.1 R69.2 R119.2 R122.1 R123.1 R129.1 R136.2 R148.2 R153.2 R158.2 R295.1 R327.2 R1207.2 R1209.1 R1210.1 R1212.2 R1214.2 R1215.2 R1217.1 SW4.1 SW4.2 SW4.4 U5.4(VSS) U6.2(GND) U10.1(GND1) U10.3(GND2) U10.20(GND3) U10.31(GND4) U10.33(GND5) U10.36(GND6) U11.33(E-Pad) U13.2(GND) U14.2(GND) U15.2(GND) U17.2(GND) U18.2(GND) U19.2(GND) U21.15(GND) U22.15(GND) U26.29(GND) U27.2(GND) XT2.2 XT2.4 XT4.2 XT4.4 XT5.2 XT5.4 ; also on sheet 4 5 6 7 8 9 10 11
GND_EARTH: C395.1 C396.1 J12.13(SH1) J12.14(SH2) ; also on sheet 4
VBAT_RTC: D4.A J3.1
VBAT_WL_1T1R: C82.2 C83.2 R71.2 U10.9(VBAT)
VCC3V3_SD_OUT: C156.2 J21.4(VDD) ; also on sheet 4
VCC3V3_SYS: C54.2 D3.A J46.1 R21.2 R22.2 R38.1 R40.2 R42.2 R46.1 R71.1 ; also on sheet 11
VCC5V0_USB_FE_D1: C129.2 J13.1 U15.1(VOUT)
VCC5V0_USB_FE_D2: C145.2 J36.1 U17.1(VOUT)
VCC5V0_USB_FE_D3: C150.2 J37.1 U18.1(VOUT)
VCC5V0_USB_FE_D4: C153.2 J38.1 U19.1(VOUT)
VCC5V0_USB_HOST1: C344.2 C346.2 J16.1(VBUS) U14.1(VOUT)
VCC5V0_USB_HOST2: C358.2 J39.1 U27.1(VOUT)
VCC5V0_USB_OTG: C341.2 C343.2 J15.1(VCC) R121.2 U13.1(VOUT)
VCC5V_SYS: R47.1 ; also on sheet 4 11
VCC_1V8_OUT: C85.2 C86.2 R65.1 R66.1 R73.1 U10.22(VDDIO) ; also on sheet 4 11
VCC_3V3_HUB: C298.2 C322.2 C324.2 C334.2 R292.2 R293.2 R294.2 R296.1 R297.1 R300.2 R301.2 R302.2 R345.2 U26.14(AVDD33) U26.21(VDD33) U26.28(VDD33)
VCC_5V: C57.2 C59.2 C123.1 C124.1 C131.2 C146.2 C151.2 C154.2 C357.2 J40.1 J41.1 J42.1 J43.1 L5.1 R346.1 U6.6(VIN) U13.5(IN) U14.5(IN) U15.5(IN) U17.5(IN) U18.5(IN) U19.5(IN) U27.5(IN) ; also on sheet 6 9 10 11
VCC_LEDA_TX1: C58.2 C60.2 D23.C J8.1 J8.2 U6.5(OVP)
VCC_LEDK_TX1: J8.9 J8.10 R48.1 R50.2 R51.2
VCC_RMII: C381.2 C391.2 R1202.2 R1203.2 R1204.1 R1211.1 R1213.2 R1218.1 R1219.2 R1225.1 R1226.2 U11.14(DVDD33)
VCCA_RMII: C380.2 C389.2 C390.2 R1225.2 U11.7(AVDD33_1) U11.30(AVDD33_2)
VDD_3V3: C55.2 C175.2 C180.2 J8.38 J8.39 R344.1 R345.1 R1226.1 U21.16(VCC) U22.16(VCC) ; also on sheet 5 6 7 8 9 10 11
VDD_RTC: C32.2 D3.C D4.C U5.8(VDD)
VDD_USB_5V: C333.2 R346.2 U26.27(V5)
CKXTALIN: C386.1 U11.32(CKXTAL-IN) XT4.3
CKXTALOUT: C387.2 U11.31(CKXTAL-OUT) XT4.1
FE1.1_DM1: R131.1 U26.3(DM1)
FE1.1_DM1_: D31.1 D31.10 J13.2 R131.2
FE1.1_DM2: R146.1 U26.6(DM2)
FE1.1_DM2_: D31.4 D31.7 J36.2 R146.2
FE1.1_DM3: R151.1 U26.12(DM3)
FE1.1_DM3_: D32.1 D32.10 J37.2 R151.2
FE1.1_DM4: R156.1 U26.15(DM4)
FE1.1_DM4_: D32.4 D32.7 J38.2 R156.2
FE1.1_DP1: R132.1 U26.4(DP1)
FE1.1_DP1_: D31.2 D31.9 J13.3 R132.2
FE1.1_DP2: R149.1 U26.7(DP2)
FE1.1_DP2_: D31.5 D31.6 J36.3 R149.2
FE1.1_DP3: R154.1 U26.13(DP3)
FE1.1_DP3_: D32.2 D32.9 J37.3 R154.2
FE1.1_DP4: R159.1 U26.16(DP4)
FE1.1_DP4_: D32.5 D32.6 J38.3 R159.2
FE1_1_DM0: R299.2 U26.1(DMU)
FE1_1_XIN: C203.2 U26.10(X1) XT5.1
FE1_1_XOUT: C202.2 U26.11(X2) XT5.3
FE2_1_DP0: R298.2 U26.2(DPU)
GMAC1_MCLKINOUT_M0: C383.2 R1224.1 ; also on sheet 4
GMAC1_MDC_M0: U11.22(MDC) ; also on sheet 4
GMAC1_MDIO_M0: R1204.2 U11.23(MDIO) ; also on sheet 4
GMAC1_RSTn: R1201.1 ; also on sheet 4
GMAC1_RXD0_M0: R1206.2 ; also on sheet 4
GMAC1_RXD1_M0: R1205.2 ; also on sheet 4
GMAC1_RXDV_CRS_M0: R1209.2 U11.26(CRS/CRS_DV) ; also on sheet 4
GMAC1_RXER_M0: R1212.1 U11.28(RXER/FXEN) ; also on sheet 4
GMAC1_TXD0_M0: U11.16(TXD0) ; also on sheet 4
GMAC1_TXD1_M0: U11.17(TXD1) ; also on sheet 4
GMAC1_TXEN_M0: U11.20(TXEN) ; also on sheet 4
GPIO0_A5_USB_OTG_PWREN: R117.2 U13.4(EN) ; also on sheet 4
GPIO0_A6_USB_OTG0_DET: R120.1 ; also on sheet 4
GPIO0_B0_u_TP_INT_L: R44.1 ; also on sheet 4
GPIO0_C7_d_TP_RST_L: R43.1 ; also on sheet 4
GPIO2_B1_WIFI_REG_ON_H: U10.12(WL_REG_ON) ; also on sheet 4
GPIO2_B2_WIFI_WAKE_HOST_H: U10.13(WL_HOST_WAKE) ; also on sheet 4
GPIO2_B7_BT_REG_ON_H: U10.34(BT_RST_N) ; also on sheet 4
GPIO2_C0_BT_WAKE_HOST_H: U10.7(BT_HOST_WAKE) ; also on sheet 4
GPIO2_C1_HOST_WAKE_BT_H: U10.6(BT_WAKE) ; also on sheet 4
GPIO4_A0_MIPI_TX1_RST_L: R342.1 ; also on sheet 4
GPIO4_B0_USB_HOST1_PWREN_H: U14.4(EN) ; also on sheet 4
GPIO4_B4_USB_FE_D4_PWREN_H: U19.4(EN) ; also on sheet 4
GPIO4_B5_HUB_XRSTJ: R343.2 ; also on sheet 4
GPIO4_B6_USB_FE_D2_PWREN_H: U17.4(EN) ; also on sheet 4
GPIO4_B7_USB_FE_D3_PWREN_H: U18.4(EN) ; also on sheet 4
GPIO4_C0_USB_HOST2_PWREN_H: U27.4(EN) ; also on sheet 4
GPIO4_C1_USB_FE_D1_PWREN_H: U15.4(EN) ; also on sheet 4
HUB_RSTJ: R343.1 U26.17(RESET#CDP)
I2C1_SCL_TP: R41.1 ; also on sheet 4
I2C1_SDA_TP: R39.1 ; also on sheet 4
I2C2_SCL_M0_RTC: R22.1 R23.2 ; also on sheet 4
I2C2_SDA_M0_RTC: R21.1 R24.2 ; also on sheet 4
I2C_SCL_RTC: R23.1 U5.6(SCL)
I2C_SDA_RTC: R24.1 U5.5(SDA)
I2S2_LRCK_TX_M0_WIFI: U10.28(PCM_SYNC) ; also on sheet 4
I2S2_SCLK_TX_M0_WIFI: U10.26(PCM_CLK) ; also on sheet 4
I2S2_SDI_M0_WIFI: U10.25(PCM_OUT) ; also on sheet 4
I2S2_SDO_M0_WIFI: U10.27(PCM_IN) ; also on sheet 4
LED0/PHYAD0: C392.2 J12.10(LEDY-) R1218.2 U11.24(LED0/PHYAD0/PMEB)
LED1/PHYAD1: C393.1 J12.11(LEDG+) R1217.2 U11.25(LED1/PHYAD1)
MIPI_DSI_TX1_CLKN: J8.27 ; also on sheet 4
MIPI_DSI_TX1_CLKP: J8.26 ; also on sheet 4
MIPI_DSI_TX1_D0N: J8.33 ; also on sheet 4
MIPI_DSI_TX1_D0P: J8.32 ; also on sheet 4
MIPI_DSI_TX1_D1N: J8.30 ; also on sheet 4
MIPI_DSI_TX1_D1P: J8.29 ; also on sheet 4
MIPI_DSI_TX1_D2N: J8.24 ; also on sheet 4
MIPI_DSI_TX1_D2P: J8.23 ; also on sheet 4
MIPI_DSI_TX1_D3N: J8.21 ; also on sheet 4
MIPI_DSI_TX1_D3P: J8.20 ; also on sheet 4
MIPI_DSI_TX1_RST: J8.36 R342.2
PHY_INT: R1219.1 U11.11(RXD2/INTB)
PMIC_32KHz_OUT_WIFI: R74.1 ; also on sheet 4
PMIC_PWRON: D82.1 D82.10 J46.2 ; also on sheet 4
PWM5_MIPI: R49.2 U6.4(EN) ; also on sheet 4
RECOVERY_KEY: C33.2 D5.1(I/O2) R25.2 SW4.3
RESETn: D82.2 D82.9 J46.3 ; also on sheet 4
RMII_CLK_: R1224.2 U11.15(TXC)
RMII_CLK_CTL: R1214.1 U11.12(RXD3/CLK_CTL)
RMII_RST_: C384.2 R1201.2 R1202.1 U11.21(PHYRSTB)
RN: D81.1 U11.6(MDI1-) U23.1(TD+)
RP: D81.3 U11.5(MDI1+) U23.3(TD-)
RXD0: R1206.1 U11.9(RXD0)
RXD1: R1205.1 R1215.1 U11.10(RXD1)
RXDV: R1213.1 U11.8(RXDV)
RXN: J12.6(RX-) U23.16(TX+)
RXP: J12.3(RX+) U23.14(TX-)
S0_RX: D43.1 D43.10 J42.2 R184.2 U22.13(R1IN)
S0_TX: D43.2 D43.9 J42.3 R183.2 U22.14(T1OUT)
S5_RX: D43.4 D43.7 J43.2 R186.2 U22.8(R2IN)
S5_TX: D43.5 D43.6 J43.3 R185.2 U22.7(T2OUT)
S7_RX: J40.2 R174.2 U21.13(R1IN)
S7_TX: J40.3 R173.2 U21.14(T1OUT)
S9_RX: J41.2 R176.2 U21.8(R2IN)
S9_TX: J41.3 R175.2 U21.7(T2OUT)
SARADC_VIN0/RECOVERY: R25.1 ; also on sheet 4
SARADC_VIN1: D82.4 D82.7 J46.4 ; also on sheet 4
SARADC_VIN2: D82.5 D82.6 J46.5 ; also on sheet 4
SDMMC0_CLK_: C155.2 D34.1 D34.10 J21.5(CLK) R160.2
SDMMC0_CLK_SD: R160.1 ; also on sheet 4
SDMMC0_CMD_SD: D33.4 D33.7 J21.3(CMD) ; also on sheet 4
SDMMC0_D0_SD: D34.2 D34.9 J21.7(DATA0) ; also on sheet 4
SDMMC0_D1_SD: D34.4 D34.7 J21.8(DATA1) ; also on sheet 4
SDMMC0_D2_SD: D33.1 D33.10 J21.1(DATA2) ; also on sheet 4
SDMMC0_D3_SD: D33.2 D33.9 J21.2(CD/DATA3) ; also on sheet 4
SDMMC0_DET_L_SD: D34.5 D34.6 J21.9(CD) R344.2 ; also on sheet 4
SDMMC1_CLK_WIFI: R67.1 ; also on sheet 4
SDMMC1_CMD_WIFI: R66.2 U10.16(SDIO_DATA_CMD) ; also on sheet 4
SDMMC1_D0_WIFI: R65.2 U10.18(SDIO_DATA_0) ; also on sheet 4
SDMMC1_D1_WIFI: U10.19(SDIO_DATA_1) ; also on sheet 4
SDMMC1_D2_WIFI: U10.14(SDIO_DATA_2) ; also on sheet 4
SDMMC1_D3_WIFI: U10.15(SDIO_DATA_3) ; also on sheet 4
TN: D81.4 U11.4(MDI0-) U23.6(RD+)
TP: D81.6 U11.3(MDI0+) U23.8(RD-)
TP1_INT: D18.2 D18.9 J8.5 J9.3 R44.2
TP1_RST: D18.1 D18.10 J8.4 J9.2 R43.2
TP1_SCL: D18.4 D18.7 J8.6 J9.4 R41.2 R42.1
TP1_SDA: D18.5 D18.6 J8.7 J9.5 R39.2 R40.1
TXN: J12.2(TX-) U23.11(RX+)
TXP: J12.1(TX+) U23.9(RX-)
UART0_RX: R184.1 R189.1 ; also on sheet 4
UART0_TX: R183.1 U22.11(T1IN) ; also on sheet 4
UART1_CTSn_M0_WIFI: R69.1 U10.41(UART_RTS_N) ; also on sheet 4
UART1_RTSn_M0_WIFI: U10.44(UART_CTS_N) ; also on sheet 4
UART1_RX_M0_WIFI: U10.42(UART_TXD) ; also on sheet 4
UART1_TX_M0_WIFI: U10.43(UART_RXD) ; also on sheet 4
UART2_RX_M0_DEBUG: R161.1 ; also on sheet 4
UART2_TX_M0_DEBUG: R162.1 ; also on sheet 4
UART5_RX_M1: R186.1 R190.1 ; also on sheet 4
UART5_TX_M1: R185.1 U22.10(T2IN) ; also on sheet 4
UART7_RX_M2: R174.1 R178.1 ; also on sheet 4
UART7_TX_M2: R173.1 U21.11(T1IN) ; also on sheet 4
UART9_RX_M2: R176.1 R177.1 ; also on sheet 4
UART9_TX_M2: R175.1 U21.10(T2IN) ; also on sheet 4
USB3_HOST1_DM: R124.1 ; also on sheet 4
USB3_HOST1_DM_2: D28.2(I/O1) J16.2(D-) R124.2
USB3_HOST1_DP: R126.1 ; also on sheet 4
USB3_HOST1_DP_2: D29.1(I/O2) J16.3(D+) R126.2
USB3_HOST1_SSRXN: R127.1 ; also on sheet 4
USB3_HOST1_SSRXP: R128.1 ; also on sheet 4
USB3_HOST1_SSTXN: C125.1 ; also on sheet 4
USB3_HOST1_SSTXP: C126.1 ; also on sheet 4
USB3_HOST1SSRXN: D30.1 D30.10 J16.5(SSRX-) R127.2
USB3_HOST1SSRXP: D30.2 D30.9 J16.6(SSRX+) R128.2
USB3_HOST1SSTXN: C125.2 D30.4 D30.7 J16.8(SSTX-)
USB3_HOST1SSTXP: C126.2 D30.5 D30.6 J16.9(SSTX+)
USB_HOST2_DM: R325.1 ; also on sheet 4
USB_HOST2_DM_: D46.1(I/O2) J39.2 R325.2
USB_HOST2_DP: R326.1 ; also on sheet 4
USB_HOST2_DP_: D47.1(I/O2) J39.3 R326.2
USB_HOST3_DM: R299.1 ; also on sheet 4
USB_HOST3_DP: R298.1 ; also on sheet 4
USB_OTG0_DM: R116.1 ; also on sheet 4
USB_OTG0_DM_2: D26.2(I/O1) J15.2(DATA+) R116.2
USB_OTG0_DP: R118.1 ; also on sheet 4
USB_OTG0_DP_2: D27.1(I/O2) J15.3(DATA-) R118.2
USB_OTG0_ID: Q5.3(DRAIN) ; also on sheet 4
USB_OTG0_VBUSDET: R120.2 R121.1 R123.2 ; also on sheet 4
WIFI1T1R_CLK: C76.2 R67.2 U10.17(SDIO_DATA_CLK)
WIFI1T1R_XTAL_IN: C78.1 U10.10(XTAL_IN) XT2.3
WIFI1T1R_XTAL_OUT: R68.2 U10.11(XTAL_OUT)
WIFIBT_32KIN_1T1R: R73.2 R74.2 U10.24(LPO)
N17053074: C77.2 C79.2 U10.2(WL_BT_ANT)
N17053234: C77.1 C80.2 J11.2(SIG)
N19277328: C181.2 U22.1(C1+)
N19277330: C181.1 U22.3(C1-)
N19277334: C182.2 U22.4(C2+)
N19277336: C182.1 U22.5(C2-)
N19277340: C183.2 U22.2(V+)
N19277344: C184.2 U22.6(V-)
N19781253: C176.2 U21.1(C1+)
N19781255: C176.1 U21.3(C1-)
N19781259: C177.2 U21.4(C2+)
N19781261: C177.1 U21.5(C2-)
N19781265: C178.2 U21.2(V+)
N19781269: C179.2 U21.6(V-)
N19781407: R177.2 U21.9(R2OUT)
N20037713: R178.2 U21.12(R1OUT)
N20144283: R189.2 U22.12(R1OUT)
N20144293: R190.2 U22.9(R2OUT)
N67159131: R136.1 U15.3(OCB)
N68563646: C30.2 U5.1(OSCI) XT1.2
N68563661: C31.2 U5.2(OSCO) XT1.1
N68693421: R148.1 U17.3(OCB)
N68696061: R153.1 U18.3(OCB)
N68696295: R158.1 U19.3(OCB)
N69863572: C81.2 R68.1 XT2.1
N69864462: C90.2 C91.2 L6.2 U10.23(VIN_LDO)
N69864477: L6.1 U10.21(VIN_LDO_OUT)
N69911722: R48.2 U6.3(FB)
N69911786: C53.2 J8.17 R38.2
N69912226: D23.A L5.2 U6.1(LX)
N69966336: J12.12(LEDG-) R1210.2
N70130938: C388.2 U11.29(DVDD10OUT)
N70266506: J12.9(LEDY+) R1211.2
N70266836: R1203.1 U11.19(TXD3)
N70527306: D35.2(I/O1) J22.1 R161.2
N70527342: D36.2(I/O1) J22.2 R162.2
N70593664: C61.1 J9.1 R46.2 R47.2
N70633183: R129.2 U14.3(OCB)
N70633229: R122.2 U13.3(OCB)
N70633628: Q5.1(GATE) R117.1 R119.1
N70676752: R295.2 U26.8(RREF)
N70676766: R301.1 U26.25(OVCUR1#)
N70676768: R300.1 U26.24(OVCUR2#)
N70676770: R293.1 U26.23(PGANG)
N70676772: R294.1 U26.22(PSELF)
N70676774: R292.1 U26.19(OVCUR4#)
N70676824: R302.1 U26.20(OVCUR3#)
N70676921: R296.2 U26.5(AVDD/NC)
N70676923: R297.2 U26.9(AVDD/NC)
N70708323: R327.1 U27.3(OCB)
N70802303: C371.2 U23.7(CT2)
N70802422: C372.2 U23.2(CT1)
N70802644: R1229.1 U23.10(CT3)
N70803761: R1228.1 U23.15(CT4)
N70846219: R1207.1 U11.1(RSET)
N70869941: C396.2 R1228.2
N70869956: C395.2 R1229.2
N76750177: C385.2 U11.2(AVDD100UT)

Not connected (* = marked no-connect by the designer): D33 5 6; D81 5*; J8 3 8 12 13 14 15 35* 40; J12 4(NC1) 5(NC2) 7(NC3) 8(NC4); J15 TH1* TH2*; U5 3(\~{IN}T) 7(CLKOUT)*; U10 4(FM_RX)* 5(N_WAKE)* 8(BT_VIO/N_HOST_WAKE)* 29(VDD_TCXO) 30(TCXO_IN)* 32(GPS_RF)* 35(N_I2C_SDA)* 37(N_I2C_SCL)* 38(N_REG_PU)* 39(TX2)* 40(TX1)* 45(N_VDDSWPIO)* 46(N_VDDSWP_OUT)* 47(N_VDDSWP_IN)*; U11 13(RXC) 18(TXD2) 27(COL); U23 4 5* 12* 13; U26 18(LED3/SCL)* 26(LED4/SDA)*

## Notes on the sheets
sheet 12
- UART/RS232
- TO SOM3566
- 串口/RS232配置
- RS232-1
- 串口/RS232配置
- RS232
- RS232-2
- 串口/RS232配置
- 串口/RS232配置
sheet 13
- RTC IC
- RECOVERY
- POWER ON/ADC
sheet 14
- MIPI_DSI_TX1
- TP COF Connector
- 100ma
sheet 15
- PHY Address/LED
- WOL/LED0 Selection
- Pull Low for LED0 Mode(default)
  Pull High for WOL Mode
- WOL:Wake-on-LAN
- 拉高可以进行网络唤醒功能
- RMII REF_CLK direction
- RMII_POWER
- Pull Low for RMII REF_CLK Output mode
  Pull High for RMII REF_CLK Input mode
- MII/RMII Selection
- Pull High for RMII mode(default)
- UTP / Fiber Selection
- Pull Low for UTP Mode(default)
  Pull High for Fiber Mode
sheet 16
- USB HUB-FE1.1
- EN>2V
sheet 17
- USB2.0 OTG
- TO SOM3566
- Current Limit：6800/R
- USB3.0 HOST1
- TO RK3566
- EN>2V
- Current Limit：6800/R
sheet 18
- SD Card
- Note:
  Take care of the type of MicroSD Card Jack,
  The type here follow the logic below:
      DET is float @ card ejected; the internal pull up decided the IO pin status
      DET is connected to GND @ card inserted
  If other type of Jack is used, need to shift the status of DET.
- TO SOM3566
- Debug UART2
sheet 19
- SDIO WIFI/BT MODULE
- 50 Ohm RF trace
- TO SOM3566
- Note:
  Adjusted the load capacitance
  according to the crystal specification.
- Diff 5ohm ± 10%
- Diff 5ohm ± 10%
- Diff 5ohm ± 10%
- Diff 5ohm ± 10%
- Diff 5ohm ± 10%
- Diff 5ohm ± 10%
- Option1
- Using RTL8189ETV/FTV modules，
  please notice
  WIFI REG ON is on pin12 or pin34,
  choose
  according to the actual condition.
- For RTL8723DS
- The maximum peak current is 600mA
  Close to WIFI module
- Option4
- Option2
- 1A_DCR<=80mohm
- WIFI
- OPTION
- a
- b/g/n
- ac
- 5GHz
- BT
- Crystals
- VDDIO
- Option1
- Option2
- Option3
- Option4
- Yes@SDIO2.0
  No@SDIO3.0
- AW-CM256SM
- Yes
- Yes
- Yes
- Yes
- 4.2
- 37.4MHz
- 1.71-3.6V
- Yes
- Yes
- Yes
- AP6236/AP6212
- No
- Yes
- No
- No
- 4.2/4.0
- 26MHz
- 1.71-3.6V
- Yes
- Yes
- No
- Yes
- Using RTL8189ETV/FTV modules，please notice
  WIFI REG ON is on pin12 or pin34, choose
  according to the actual condition.
- Yes@SDIO2.0
  No@SDIO3.0
- AP6256/AP6255
- Yes
- Yes
- Yes
- Yes
- 5.0/4.2
- 37.4MHz
- 1.71-3.6V
- Yes
- Yes
- Yes
- RTL8189ETV
  Module F89FTSM12-W3
- No
- Yes
- No
- No
- No
- Module
  Integrated
- 1.8-3.3V
- No
- No
- No
- No
- RTL8723BS
  Module F23BDSM23-W2
- No
- Yes
- No
- No
- 4.0
- Module
  Integrated
- 1.62-3.6V
- No
- No
- No
- No
- Note:
  Yes: option circuit be mounted
  No:  option circuit not be mounted
- RTL8723DS
  Module 6223A-SRD
- No
- Yes
- No
- No
- 4.2
- Module
  Integrated
- 1.62-3.6V
- No
- No
- No
- No
- QCA9377
  Module 8223A-SR
- Yes
- Yes
- Yes
- Yes
- 4.2
- Module
  Integrated
- 1.7-3.45V
- No
- No
- No
- Yes
- RTL8821CS
  Module 6221A-SRC
- Yes
- Yes
- Yes
- Yes
- 4.2
- Module
  Integrated
- 1.7-3.45V
- No
- No
- No
- No
